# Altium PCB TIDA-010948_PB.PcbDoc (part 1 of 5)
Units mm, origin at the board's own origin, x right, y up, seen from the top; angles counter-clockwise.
Board outline 140 x 180 mm, 4 copper layers (Top Layer, Mid-Layer 1, Mid-Layer 2, Bottom Layer), stack 1.554 mm thick; 481 components, 274 nets, 1278 pads, 301 vias.
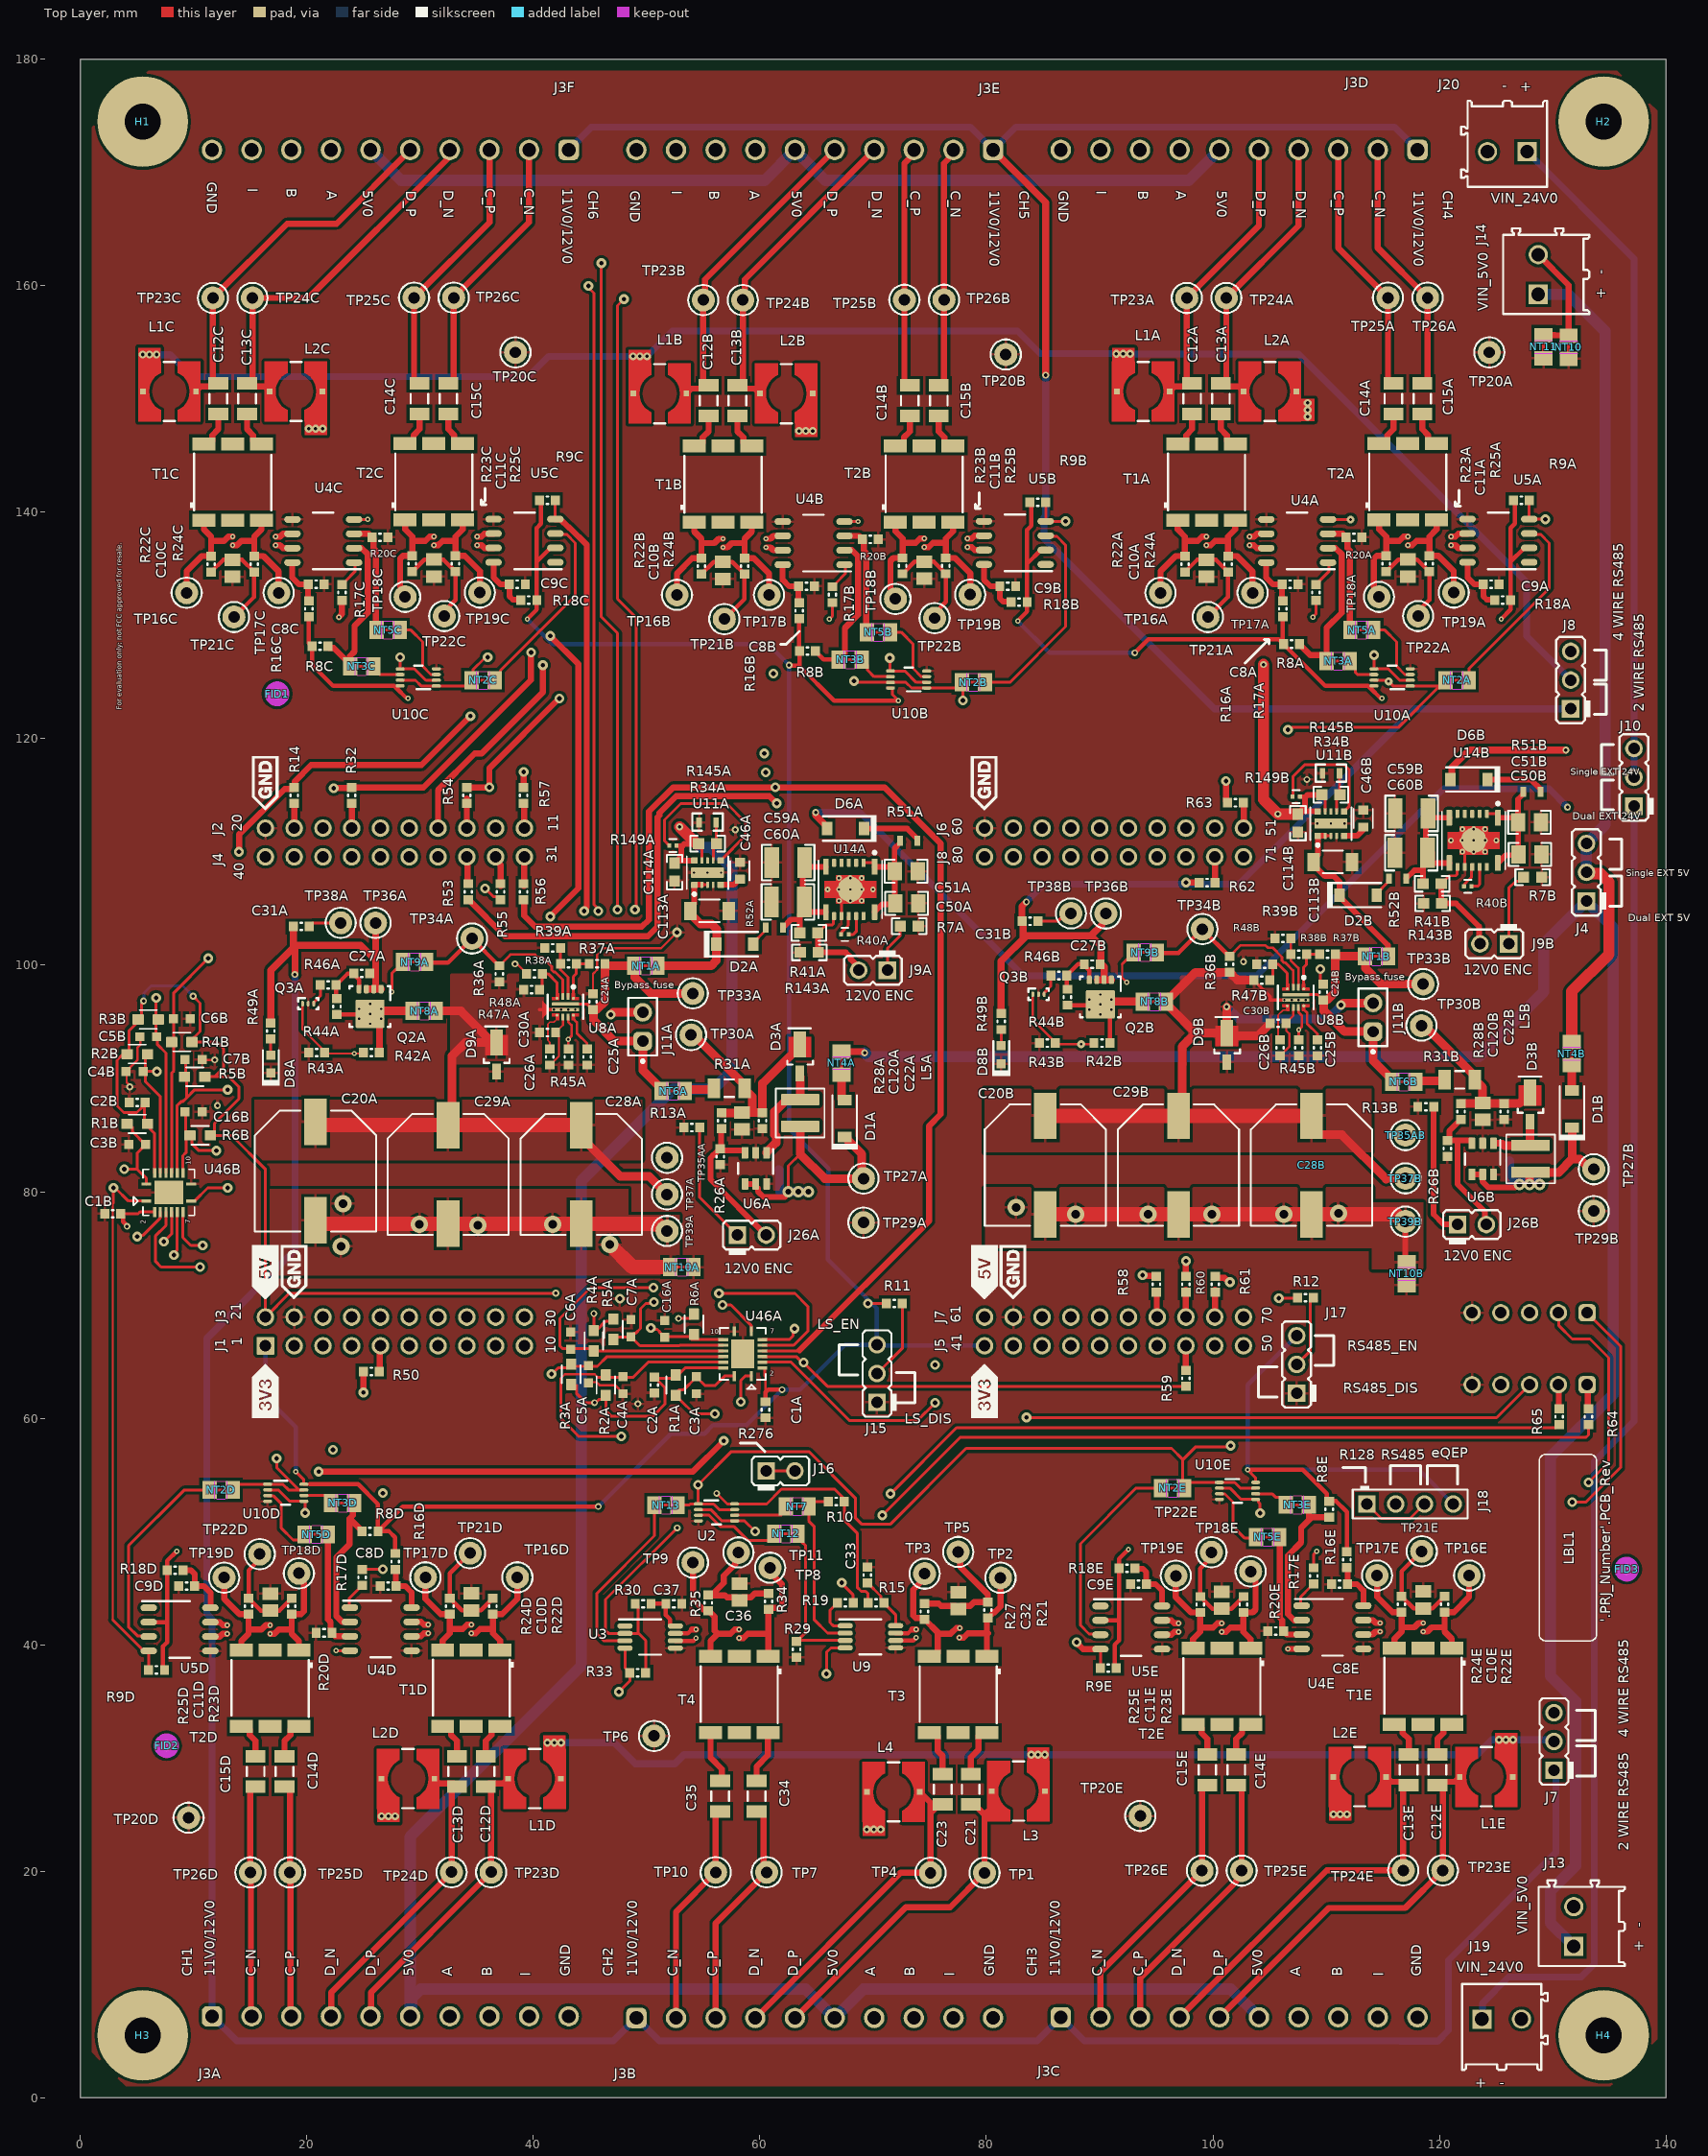
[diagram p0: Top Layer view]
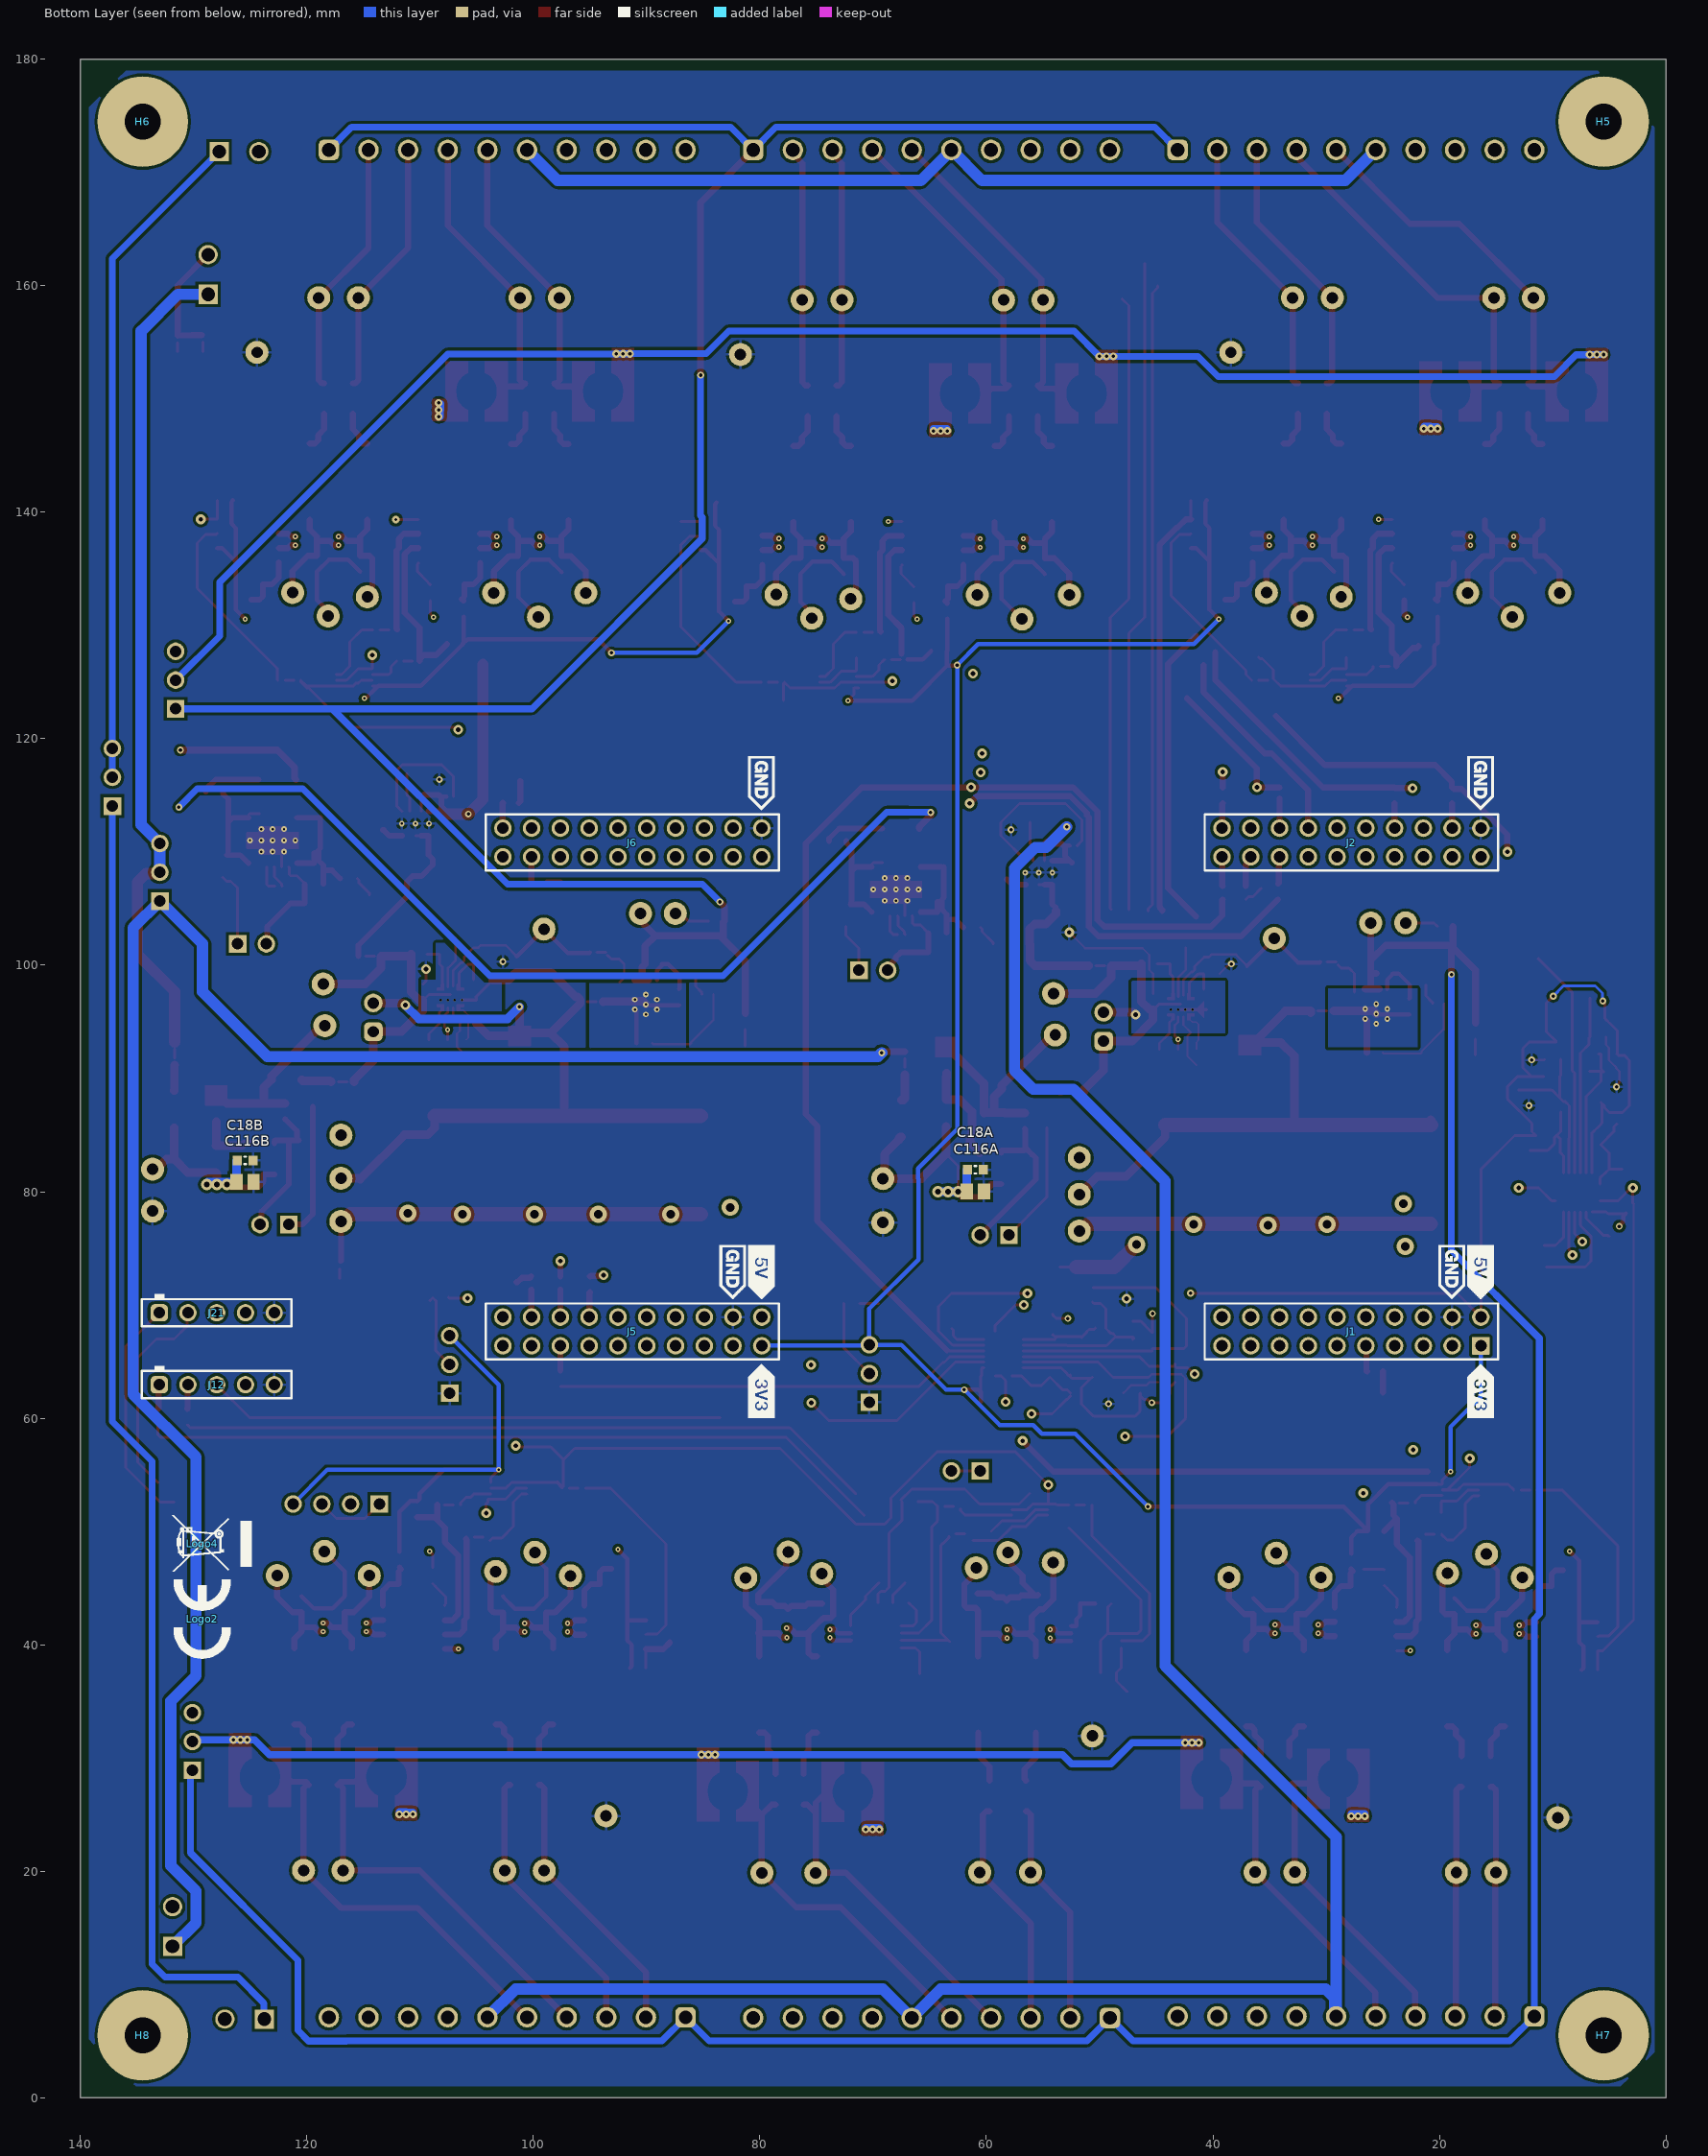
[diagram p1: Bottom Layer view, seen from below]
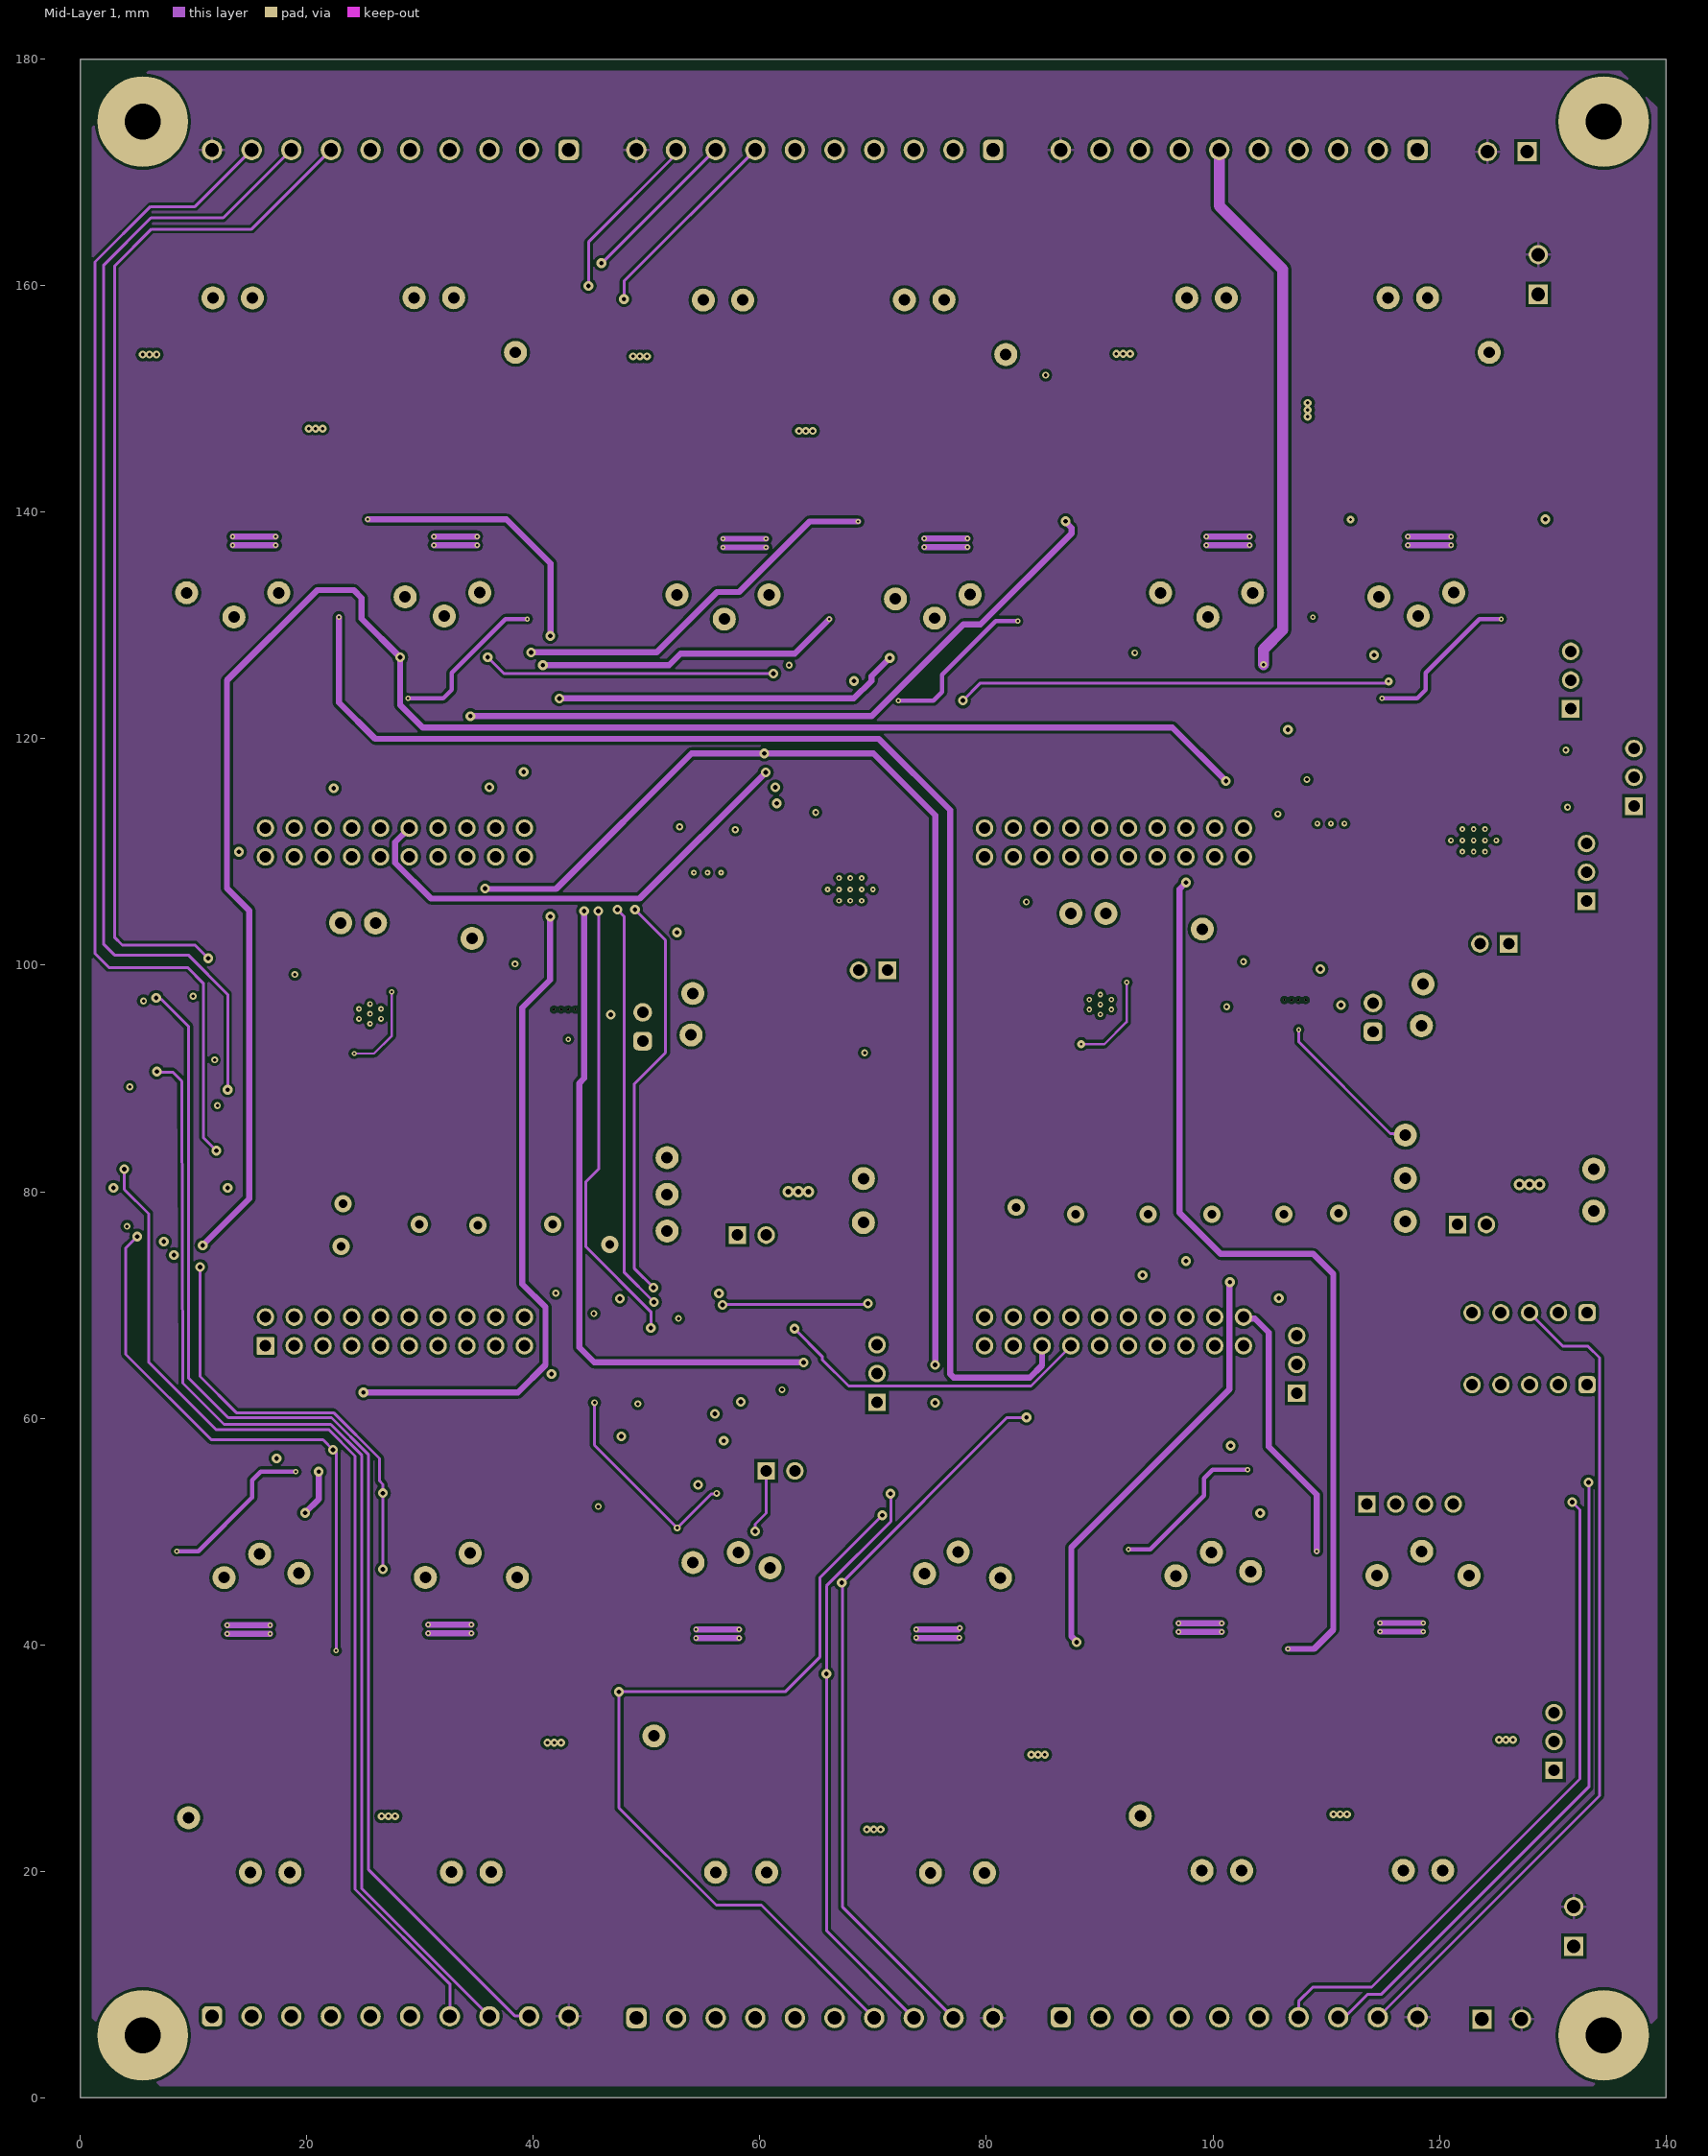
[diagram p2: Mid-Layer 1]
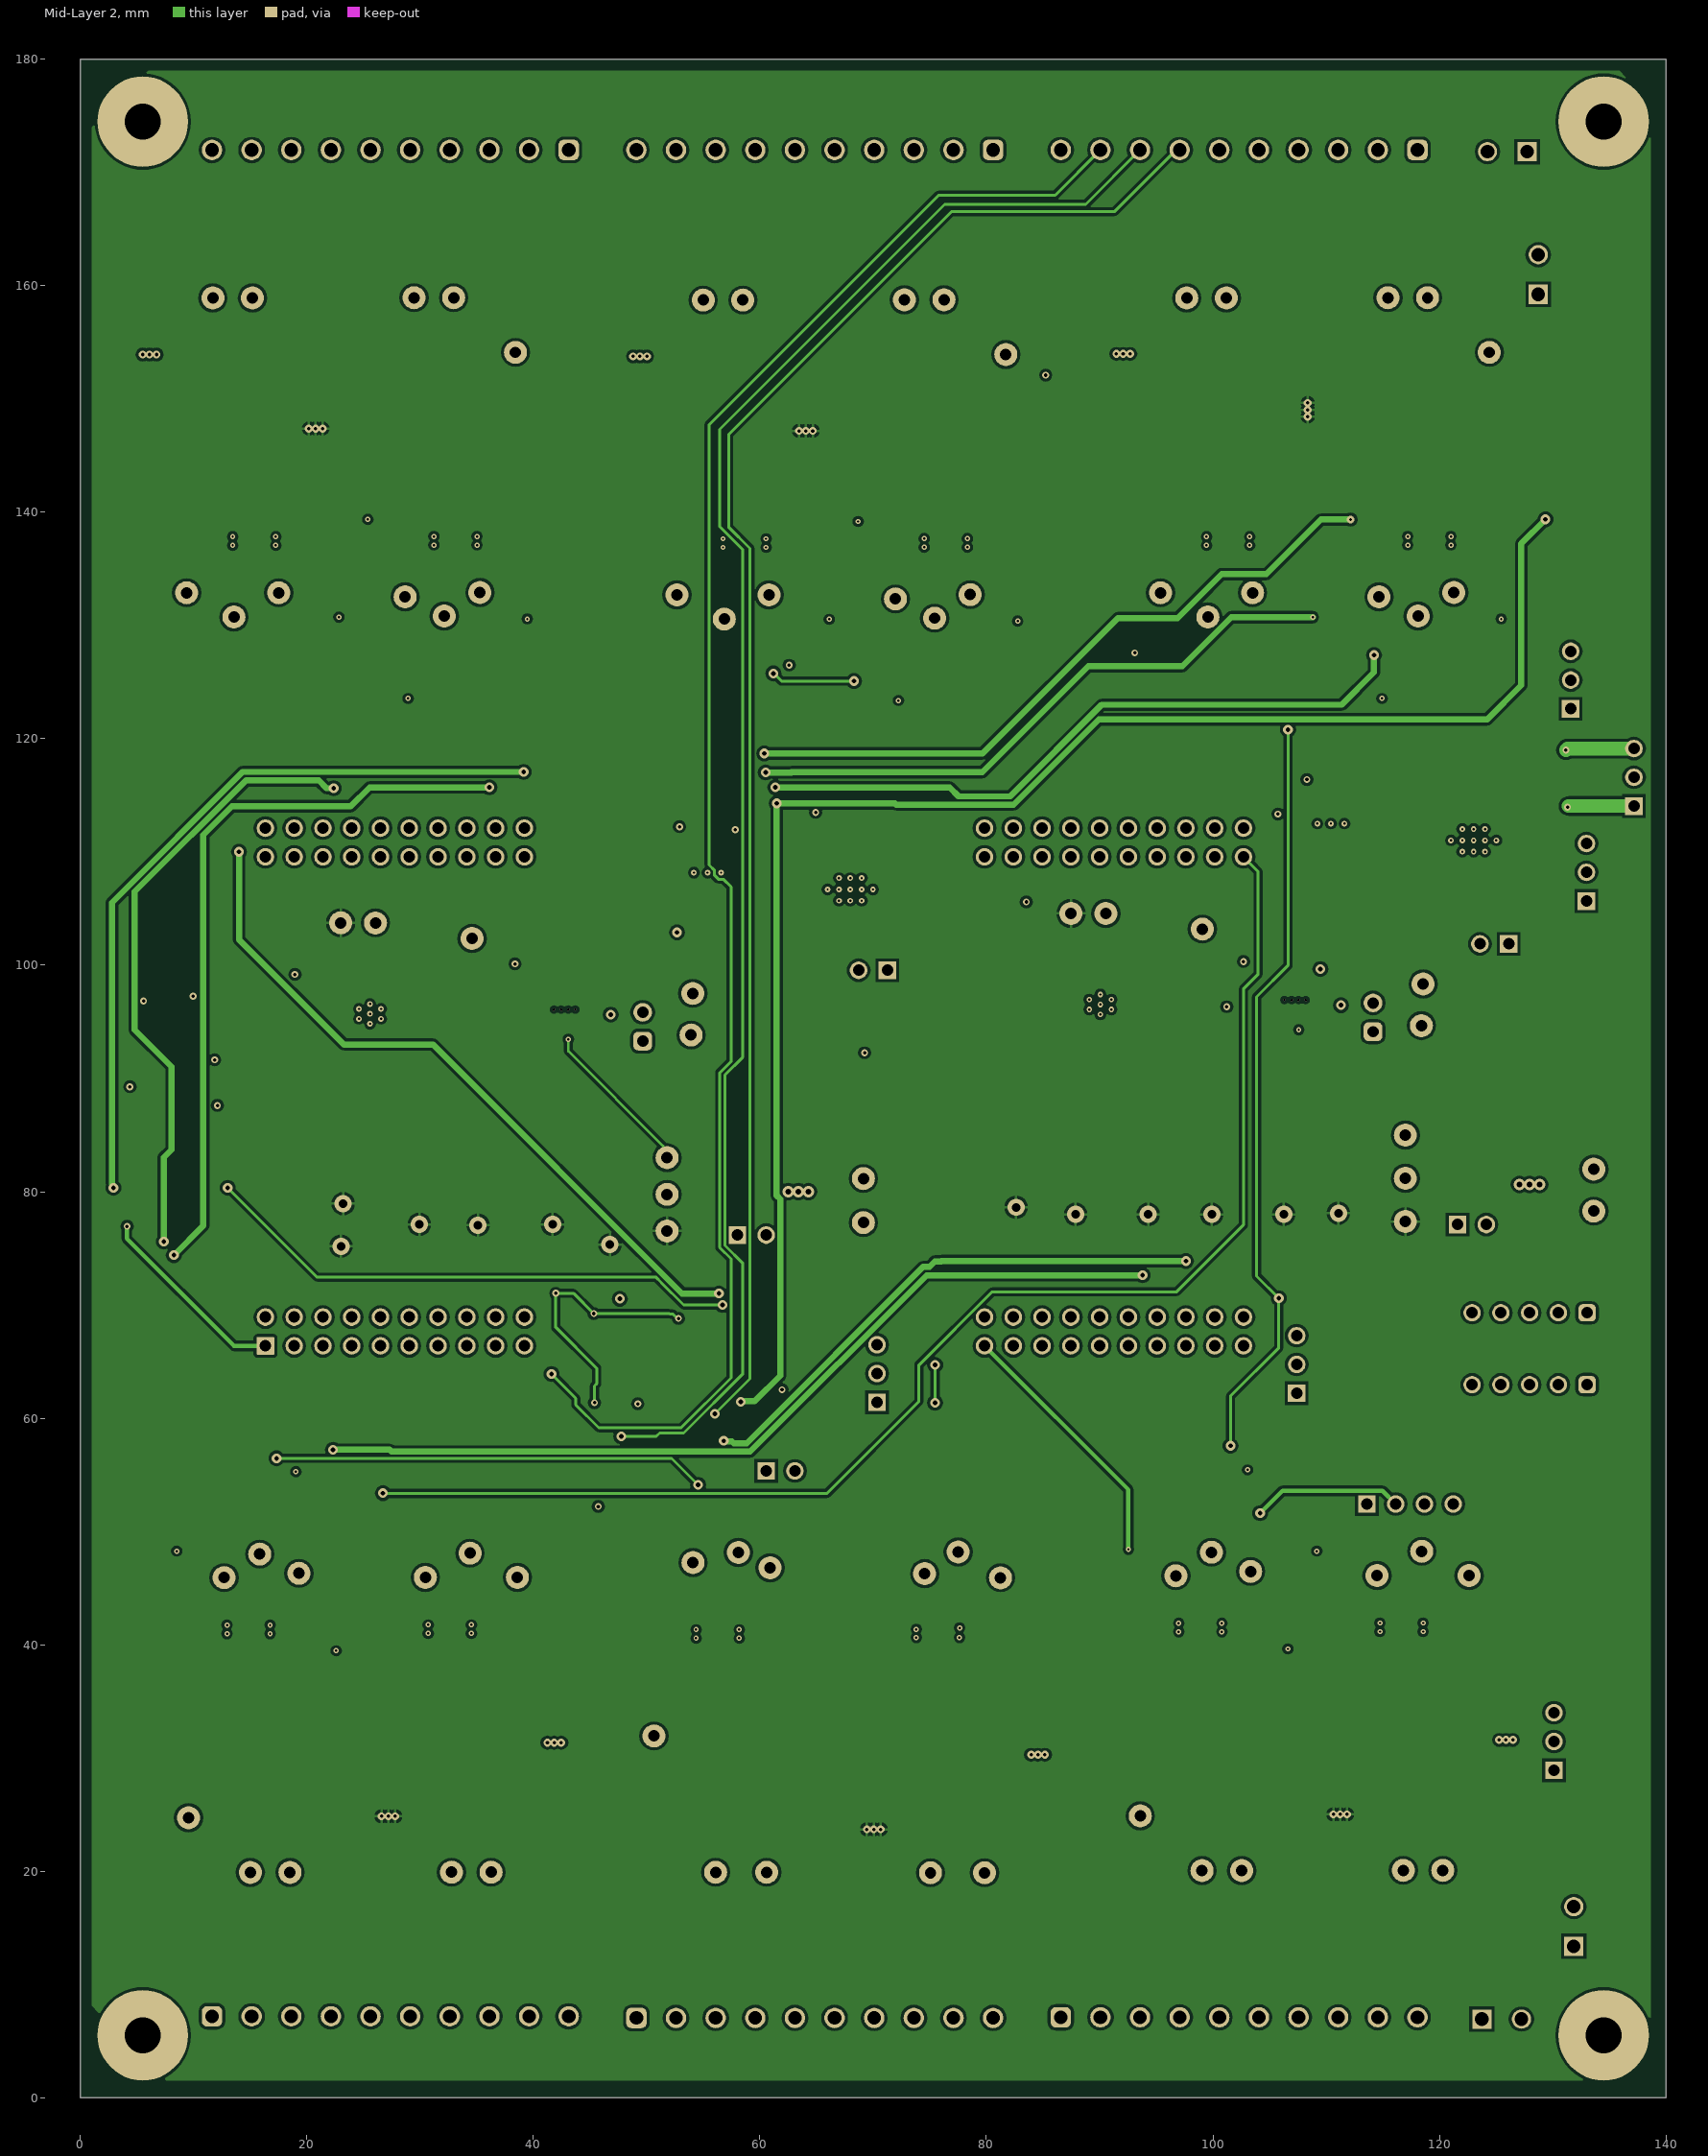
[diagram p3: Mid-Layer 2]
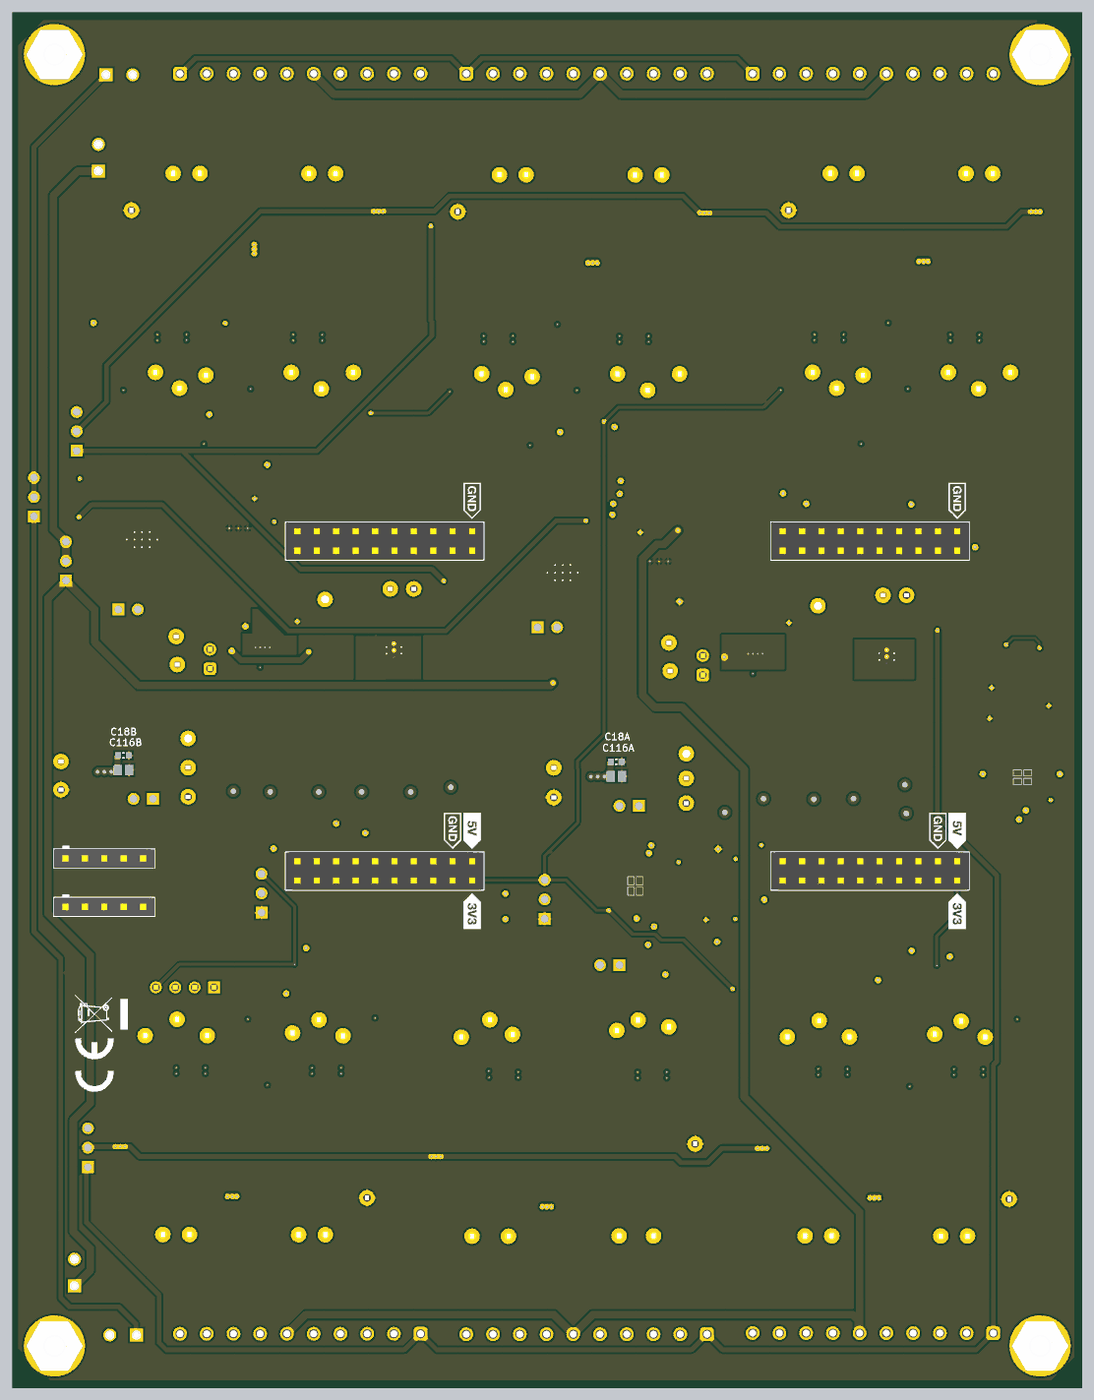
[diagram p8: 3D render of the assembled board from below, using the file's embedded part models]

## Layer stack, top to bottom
Top Solder: solder mask 0.0102, Solder Resist, Dk 3.5
Top Layer: signal copper 0.0356
Dielectric2: dielectric 0.254, FR-4, Dk 4.2
Mid-Layer 1: signal copper 0.0356
Dielectric1: core 0.9034, FR-4 High Tg, Dk 4.2
Mid-Layer 2: signal copper 0.0356
Dielectric3: dielectric 0.254, FR-4, Dk 4.2
Bottom Layer: signal copper 0.0356
Bottom Solder: solder mask 0.0102, Solder Resist, Dk 3.5

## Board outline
0,0 140,0 140,180 0,180

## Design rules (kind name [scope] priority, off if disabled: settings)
AcuteAngle [All] p1: minimum=4.50000000000000E+0001 checktracksonly=FALSE
AssemblyTestPointUsage [All] p1: valid=2
BoardOutlineClearance BoardOutlineClearance_MountingHoles [OnCopper and InComponentClass('Mounting Holes')] p1: gap=1 ignorepadtopadclearanceinfootprint=FALSE
BoardOutlineClearance BoardOutlineClearance_Poly [OnCopper and IsPoly] p2: gap=0.635 ignorepadtopadclearanceinfootprint=FALSE
BoardOutlineClearance [OnCopper and Not InComponentClass('Logo') and not InComponentClass('FiducialMark') and not InRegion(1000,500,4000,800) and not InPoly] p3: gap=1.016 ignorepadtopadclearanceinfootprint=FALSE
Clearance Clearance_Keepouts [((IsTrack Or IsArc) And Not InPoly) And IsFree and IsKeepOut vs ((IsTrack Or IsArc) And Not InPoly) And IsFree and IsKeepOut] p1: gap=0 ignorepadtopadclearanceinfootprint=FALSE
Clearance Clearance_Poly [InPolygon] p2: gap=0.254 ignorepadtopadclearanceinfootprint=TRUE
Clearance Clearance_FiducialMark [IsKeepOut and InComponentClass('FiducialMark') vs IsPad and InComponentClass('FiducialMark')] p3: gap=0 ignorepadtopadclearanceinfootprint=FALSE
Clearance [All] p4: gap=0.2 ignorepadtopadclearanceinfootprint=TRUE
ComponentClearance ComponentClearance_MountingHoles_FiducialMarks [InComponentClass('Mounting Holes') vs InComponentClass('FiducialMark')] p1: gap=1.27 collisioncheckmode=3 verticalgap=0.254 showdistances=FALSE
ComponentClearance ComponentClearance_Shunt [InComponentClass('Header') vs InComponentClass('Shunt')] p2: gap=0 collisioncheckmode=3 verticalgap=0 showdistances=FALSE
ComponentClearance ComponentClearance_Logo [InComponentClass('Logo')] p3: gap=0.762 collisioncheckmode=3 verticalgap=0.254 showdistances=FALSE
ComponentClearance ComponentClearance_ScrewToNut [(HasFootprint('NY PMS 440 0025 PH')) vs (HasFootprint('Keystone_1902C'))] p4: gap=0.127 collisioncheckmode=3 verticalgap=0.254 showdistances=FALSE
ComponentClearance ComponentClearance_MountingHoles [InComponentClass('Mounting Holes')] p5: gap=2.54 collisioncheckmode=3 verticalgap=2540 showdistances=FALSE
ComponentClearance ComponentClearance_SmallPassives [HasFootprint('0201*') or HasFootprint('0402*') or HasFootprint('0508') or HasFootprint('0603*') or HasFootprint('0612') or HasFootprint('0805*') or HasFootprint('0815*') or HasFootprint('0830*') or HasFootprint('1206*') or HasFootprint('1210*') or HasFootprint('1808*') or HasFootprint('1812*') or HasFootprint('1825*') or HasFootprint('2010*') or HasFootprint('2220*') or HasFootprint('2225*') or HasFootprint('2512*') or HasFootprint('2728*') or HasFootprint('3518*') vs HasFootprint('0201*') or HasFootprint('0402*') or HasFootprint('0508') or HasFootprint('0603*') or HasFootprint('0612') or HasFootprint('0805*') or HasFootprint('0815*') or HasFootprint('0830*') or HasFootprint('1206*') or HasFootprint('1210*') or HasFootprint('1808*') or HasFootprint('1812*') or HasFootprint('1825*') or HasFootprint('2010*') or HasFootprint('2220*') or HasFootprint('2225*') or HasFootprint('2512*') or HasFootprint('2728*') or HasFootprint('3518*')] p6: gap=0.38 collisioncheckmode=3 verticalgap=0.254 showdistances=FALSE
ComponentClearance ComponentClearance_THtoSMT [IsThruComponent vs IsSMTComponent] p7: gap=0.762 collisioncheckmode=3 verticalgap=0.762 showdistances=FALSE
ComponentClearance ComponentClearance_THtoTH [IsThruComponent vs IsThruComponent] p8: gap=0.508 collisioncheckmode=3 verticalgap=0.762 showdistances=FALSE
ComponentClearance [All] p9: gap=0.508 collisioncheckmode=3 verticalgap=0.254 showdistances=FALSE
FabricationTestPointUsage TestPointUsage [All] p1: valid=2 allowmultiple=FALSE
FabricationTestpoint Testpoint [All] p1: side=3 testpointundercomponent=TRUE minsize=1.016 maxsize=2.54 preferedsize=1.524 minholesize=0 maxholesize=1.016 preferedholesize=0.813 testpointgrid=0.025 allowsidetop=TRUE allowsidebottom=TRUE usegrid=TRUE gridtolerance=0
FanoutControl Fanout_LCC [IsLCC] p1: bgadir=Out bgaviamode=Centered fanoutstyle=Auto fanoutdirection=Alternating viagrid=0.025 // Fanout_LCC (Default Rule)
FanoutControl Fanout_BGA [IsBGA] p2: bgadir=Out bgaviamode=Centered fanoutstyle=Auto fanoutdirection=Alternating viagrid=0.025 // Fanout_BGA (Default Rule)
FanoutControl Fanout_Default [All] p4: bgadir=Out bgaviamode=Centered fanoutstyle=Auto fanoutdirection=Alternating viagrid=0.025 // Fanout_Default (Default Rule)
FanoutControl Fanout_Small [(CompPinCount < 5)] p5: bgadir=Out bgaviamode=Centered fanoutstyle=Auto fanoutdirection=OutThenIn viagrid=0.025 // Fanout_Small (Default Rule)
HoleSize [All] p1: absolutevalues=TRUE maxlimit=6.375 minlimit=0.2 maxpercent=80.000 minpercent=20.000
MinimumAnnularRing MinimumAnnularRing_ThermalPadVias [IsVia and InAnyComponent] p1: minimumring=0.15
MinimumAnnularRing [All] p2: minimumring=0.2
MinimumSolderMaskSliver MinimumSolderMaskSliver_Logo [InComponentClass('Logo') vs InComponentClass('Logo')] p1: minsoldermaskwidth=0.018
MinimumSolderMaskSliver [All] p2: minsoldermaskwidth=0.1
PlaneConnect [All] p1: planeconnectstyle=Relief reliefexpansion=0.254 reliefentries=4 reliefconductorwidth=0.254 reliefairgap=0.254
PolygonConnect [All] p1: connectstyle=Relief reliefconductorwidth=0.254 reliefentries=4 polygonreliefangle="90 Angle" airgapwidth=0.254
RoomDefinition RoomDefinition_8 [InComponentClass('U_Buck_converters2')] p1: confinementstyle=ConfineIn formatcopy=TRUE lockcomponents=FALSE outline 130.179,104.372 106.118,104.372 106.118,117.934 130.179,117.934
RoomDefinition RoomDefinition_9 [InComponentClass('U_Level_shifter_2')] p2: confinementstyle=ConfineIn formatcopy=TRUE lockcomponents=FALSE outline 1.649,77.186 1.649,96.196 11.962,96.196 11.962,77.186
RoomDefinition RoomDefinition_3 [InComponentClass('U_Communication_2')] p3: confinementstyle=ConfineIn formatcopy=TRUE lockcomponents=FALSE outline 88.3,122.813 46.3,122.813 46.3,160.813 88.3,160.813
RoomDefinition RoomDefinition_4 [InComponentClass('U_Communication_3')] p4: confinementstyle=ConfineIn formatcopy=TRUE lockcomponents=FALSE outline 45,123 3,123 3,161 45,161
RoomDefinition RoomDefinition_2 [InComponentClass('U_Communication_1')] p5: confinementstyle=ConfineIn formatcopy=TRUE lockcomponents=FALSE outline 131,123 89,123 89,161 131,161
RoomDefinition RoomDefinition_10 [InComponentClass('U_Level_shifter_1')] p6: confinementstyle=ConfineIn formatcopy=TRUE lockcomponents=FALSE outline 61.364,59.543 42.355,59.543 42.355,69.857 61.364,69.857
RoomDefinition RoomDefinition_7 [InComponentClass('U_Buck_converters1')] p7: confinementstyle=ConfineIn formatcopy=TRUE lockcomponents=FALSE outline 75.133,100.045 51.071,100.045 51.071,113.607 75.133,113.607
RoomDefinition [InComponentClass('U_Power_2')] p8: confinementstyle=ConfineIn formatcopy=TRUE lockcomponents=FALSE outline 135.388,73.026 79.28,73.026 79.28,106.169 135.388,106.169
RoomDefinition RoomDefinition_1 [InComponentClass('U_Power_1')] p9: confinementstyle=ConfineIn formatcopy=TRUE lockcomponents=FALSE outline 70.894,72.197 14.787,72.197 14.787,105.341 70.894,105.341
RoomDefinition RoomDefinition_11 [InComponentClass('U_Communication_5V0')] p10: confinementstyle=ConfineIn formatcopy=TRUE lockcomponents=FALSE outline 86.559,17.927 45.559,17.927 45.559,56.509 86.559,56.509
RoomDefinition RoomDefinition_6 [InComponentClass('U_Communication_5')] p11: confinementstyle=ConfineIn formatcopy=TRUE lockcomponents=FALSE outline 87,56 129,56 129,18 87,18
RoomDefinition RoomDefinition_5 [InComponentClass('U_Communication_4')] p12: confinementstyle=ConfineIn formatcopy=TRUE lockcomponents=FALSE outline 2.958,55.837 44.958,55.837 44.958,17.837 2.958,17.837
RoutingLayers RoutingLayers_1 [All] p1: top layer_v5=TRUE mid layer 1_v5=TRUE mid layer 2_v5=TRUE bottom layer_v5=TRUE
RoutingVias [All] p1: holewidth=0.711 width=1.27 viastyle="Through Hole" minholewidth=0.711 minwidth=1.27 maxholewidth=0.711 maxwidth=1.27
SilkToBoardRegionClearance [Not ((IsComment or IsDesignator) And (Hide <> 'False')) and not InRegion(1000,500,4000,800)] p1:
SilkToSilkClearance SilkToSilkClearance_Pb-FreeLogo [(HasFootprint('Pb-Free_Overlay_Medium') OR HasFootprint('Pb-Free_Overlay_Small')) vs (HasFootprint('Pb-Free_Overlay_Medium') OR HasFootprint('Pb-Free_Overlay_Small'))] p1: silktosilkclearance=0
SilkToSilkClearance [All] p2: silktosilkclearance=0.1
SilkToSolderMaskClearance SilkToComponentPadClearance [(IsPad or IsFill or IsRegion) and InAnycomponent] p1: minsilkscreentomaskgap=0.127 clearancetoexposedcopper=TRUE
SilkToSolderMaskClearance "Silk to Solder Mask Opening" [All] p2: minsilkscreentomaskgap=0.1 clearancetoexposedcopper=FALSE
SolderMaskExpansion [All] p1: expansion=0.05 istentingtop=FALSE
SupplyNets "Schematic Supply Nets_4" [InNet('GND_EXT')] p1: voltage=0.000
SupplyNets "Schematic Supply Nets_3" [InNet('GND_ENC')] p2: voltage=0.000
SupplyNets "Schematic Supply Nets_2" [InNet('LP_3V3')] p3: voltage=0.000
SupplyNets "Schematic Supply Nets_1" [InNet('GND')] p4: voltage=0.000
SupplyNets "Schematic Supply Nets" [InNet('LP_5V0')] p5: voltage=0.000
UnRoutedNet [All] p1: checkbadconnections=TRUE
UnpouredPolygon UnpouredPolygon_1 [All] p1:
UnpouredPolygon [All] p2:
Width [All] p1: maxlimit=0.254 minlimit=0.254 preferedwidth=0.254
13 further rules are at their usual default settings.

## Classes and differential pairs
channel class TIDA-010948_PB_Power: U_Power_1 U_Power_2
channel class TIDA-010948_PB_Level_shifter: U_Level_shifter_1 U_Level_shifter_2
channel class TIDA-010948_PB_Encoder_connector: U_Encoder_connector_1 U_Encoder_connector_2 U_Encoder_connector_3 U_Encoder_connector_4 U_Encoder_connector_5 U_Encoder_connector_6
channel class TIDA-010948_PB_Communication: U_Communication_1 U_Communication_2 U_Communication_3 U_Communication_4 U_Communication_5
channel class TIDA-010948_PB_Buck_converters: U_Buck_converters1 U_Buck_converters2
polygon class PolyDirectConnect: BOTTOM_LAYER_GND_P089 BOTTOM_LAYER_GND_P096 BOTTOM_LAYER_NETNT8A_2_P080 BOTTOM_LAYER_NETNT8B_2_P088 BOTTOM_LAYER_V_BULKA_P083 BOTTOM_LAYER_V_BULKB_P090
component class U_Buck_converters2: C46B C50B C51B C59B C60B C113B C114B D2B D6B J9B R7B R34B R40B R41B R51B R52B R143B R145B R149B U11B U14B
component class U_Buck_converters1: C46A C50A C51A C59A C60A C113A C114A D2A D6A J9A R7A R34A R40A R41A R51A R52A R143A R145A R149A U11A U14A
component class U_Communication_4: C8D C9D C10D C11D C12D C13D C14D C15D L1D L2D NT2D NT3D NT5D R8D R9D R16D R17D R18D R20D R22D R23D R24D R25D T1D T2D TP16D TP17D TP18D TP19D TP20D TP21D TP22D TP23D TP24D TP25D TP26D U4D U5D U10D
component class U_Communication_5: C8E C9E C10E C11E C12E C13E C14E C15E L1E L2E NT2E NT3E NT5E R8E R9E R16E R17E R18E R20E R22E R23E R24E R25E T1E T2E TP16E TP17E TP18E TP19E TP20E TP21E TP22E TP23E TP24E TP25E TP26E U4E U5E U10E
component class U_Communication_5V0: C21 C23 C32 C33 C34 C35 C36 C37 L3 L4 NT7 NT12 NT13 R10 R15 R19 R21 R27 R29 R30 R33 R34 R35 T3 T4 TP1 TP2 TP3 TP4 TP5 TP6 TP7 TP8 TP9 TP10 TP11 U2 U3 U9
component class TIDA-010948_PB: J7 J8 J15 J16 J17 J18 R11 R12
component class U_Level_shifter_2: C1B C2B C3B C4B C5B C6B C7B C16B R1B R2B R3B R4B R5B R6B U46B
component class U_Level_shifter_1: C1A C2A C3A C4A C5A C6A C7A C16A R1A R2A R3A R4A R5A R6A U46A
component class U_Encoder_connector_6: J3F
component class U_Encoder_connector_5: J3E
component class U_Encoder_connector_4: J3D
component class U_Encoder_connector_3: J3C
component class U_Encoder_connector_2: J3B
component class U_Encoder_connector_1: J3A
component class U_Connectors: J1 J2 J4 J5 J6 J10 J12 J13 J14 J19 J20 J21 NT10 NT11 R14 R32 R50 R53 R54 R55 R56 R57 R58 R59 R60 R61 R62 R63 R64 R65
component class U_Communication_3: C8C C9C C10C C11C C12C C13C C14C C15C L1C L2C NT2C NT3C NT5C R8C R9C R16C R17C R18C R20C R22C R23C R24C R25C T1C T2C TP16C TP17C TP18C TP19C TP20C TP21C TP22C TP23C TP24C TP25C TP26C U4C U5C U10C
component class U_Communication_2: C8B C9B C10B C11B C12B C13B C14B C15B L1B L2B NT2B NT3B NT5B R8B R9B R16B R17B R18B R20B R22B R23B R24B R25B T1B T2B TP16B TP17B TP18B TP19B TP20B TP21B TP22B TP23B TP24B TP25B TP26B U4B U5B U10B
component class U_Power_2: C18B C20B C22B C24B C25B C26B C27B C28B C29B C30B C31B C116B C120B D1B D3B D8B D9B J11B J26B L5B NT1B NT4B NT6B NT8B NT9B NT10B Q2B Q3B R13B R26B R28B R31B R36B R37B R38B R39B R42B R43B R44B R45B R46B R47B R48B R49B TP27B TP29B TP30B TP33B TP34B TP35AB TP36B TP37B TP38B TP39B U6B U8B
component class U_Power_1: 2 C18A C20A C22A C24A C25A C26A C27A C28A C29A C30A C31A C116A C120A D1A D3A D8A D9A J11A J26A L5A NT1A NT4A NT6A NT8A NT9A NT10A Q2A Q3A R13A R26A R28A R31A R36A R37A R38A R39A R42A R43A R44A R45A R46A R47A R48A R49A TP27A TP29A TP30A TP33A TP34A TP35AA TP36A TP37A TP38A TP39A U6A U8A
component class U_Communication_1: C8A C9A C10A C11A C12A C13A C14A C15A L1A L2A NT2A NT3A NT5A R8A R9A R16A R17A R18A R20A R22A R23A R24A R25A T1A T2A TP16A TP17A TP18A TP19A TP20A TP21A TP22A TP23A TP24A TP25A TP26A U4A U5A U10A
component class U_Hardware: FID1 FID2 FID3 H1 H2 H3 H4 H5 H6 H7 H8 LBL1 Logo2 Logo3 Logo4 ZZ1 ZZ2 ZZ3 ZZ4

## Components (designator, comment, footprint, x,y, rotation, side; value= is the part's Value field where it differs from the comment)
C1A "GRM188R72A104KA35D" 0603L 60.491,60.744 r270 top value=0.1uF (schematic designator C1)
C1B "GRM188R72A104KA35D" 0603L 2.85,78.059 r180 top value=0.1uF (schematic designator C1)
C2A "GRM188R72A104KA35D" 0603L 50.668,62.914 r270 top value=0.1uF (schematic designator C2)
C2B "GRM188R72A104KA35D" 0603L 5.02,87.882 r180 top value=0.1uF (schematic designator C2)
C3A "885012006085" WCAP-CSGP_0603_L1.6W0.8H0.8_Reflow 54.393,62.914 r270 top (schematic designator C3)
C3B "885012006085" WCAP-CSGP_0603_L1.6W0.8H0.8_Reflow 5.02,84.157 r180 top (schematic designator C3)
C4A "885012006085" WCAP-CSGP_0603_L1.6W0.8H0.8_Reflow 47.926,62.914 r270 top (schematic designator C4)
C4B "885012006085" WCAP-CSGP_0603_L1.6W0.8H0.8_Reflow 4.784,90.6 r180 top (schematic designator C4)
C5A "885012006085" WCAP-CSGP_0603_L1.6W0.8H0.8_Reflow 44.865,63.878 r270 top (schematic designator C5)
C5B "885012006085" WCAP-CSGP_0603_L1.6W0.8H0.8_Reflow 5.984,93.685 r180 top (schematic designator C5)
C6A "885012006085" WCAP-CSGP_0603_L1.6W0.8H0.8_Reflow 43.285,66.843 r90 top (schematic designator C6)
C6B "885012006085" WCAP-CSGP_0603_L1.6W0.8H0.8_Reflow 8.949,95.265 r0 top (schematic designator C6)
C7A "885012006085" WCAP-CSGP_0603_L1.6W0.8H0.8_Reflow 48.608,67.943 r90 top (schematic designator C7)
C7B "885012006085" WCAP-CSGP_0603_L1.6W0.8H0.8_Reflow 9.993,91.685 r0 top (schematic designator C7)
C8A "GRM188R72A104KA35D" 0603L 106.805,133.657 r0 top value=0.1uF (schematic designator C8)
C8B "GRM188R72A104KA35D" 0603L 64.106,133.47 r0 top value=0.1uF (schematic designator C8)
C8C "GRM188R72A104KA35D" 0603L 20.805,133.657 r0 top value=0.1uF (schematic designator C8)
C8D "GRM188R72A104KA35D" 0603L 27.153,45.181 r180 top value=0.1uF (schematic designator C8)
C8E "GRM188R72A104KA35D" 0603L 111.195,45.343 r180 top value=0.1uF (schematic designator C8)
C9A "GRM188R72A104KA35D" 0603L 124.585,133.657 r0 top value=0.1uF (schematic designator C9)
C9B "GRM188R72A104KA35D" 0603L 81.886,133.47 r0 top value=0.1uF (schematic designator C9)
C9C "GRM188R72A104KA35D" 0603L 38.585,133.657 r0 top value=0.1uF (schematic designator C9)
C9D "GRM188R72A104KA35D" 0603L 9.373,45.181 r180 top value=0.1uF (schematic designator C9)
C9E "GRM188R72A104KA35D" 0603L 93.415,45.343 r180 top value=0.1uF (schematic designator C9)
C10A "CGA4J3X7R1H225K125AB" 0805L 99.439,135.054 r270 top value=2.2uF (schematic designator C10)
C10B "CGA4J3X7R1H225K125AB" 0805L 56.74,134.867 r270 top value=2.2uF (schematic designator C10)
C10C "CGA4J3X7R1H225K125AB" 0805L 13.439,135.054 r270 top value=2.2uF (schematic designator C10)
C10D "CGA4J3X7R1H225K125AB" 0805L 34.519,43.784 r90 top value=2.2uF (schematic designator C10)
C10E "CGA4J3X7R1H225K125AB" 0805L 118.561,43.946 r90 top value=2.2uF (schematic designator C10)
C11A "CGA4J3X7R1H225K125AB" 0805L 117.208,135.074 r270 top value=2.2uF (schematic designator C11)
C11B "CGA4J3X7R1H225K125AB" 0805L 74.508,134.887 r270 top value=2.2uF (schematic designator C11)
C11C "CGA4J3X7R1H225K125AB" 0805L 31.208,135.074 r270 top value=2.2uF (schematic designator C11)
C11D "CGA4J3X7R1H225K125AB" 0805L 16.75,43.763 r90 top value=2.2uF (schematic designator C11)
C11E "CGA4J3X7R1H225K125AB" 0805L 100.792,43.926 r90 top value=2.2uF (schematic designator C11)
C12A "ECPU1C474MA5" 1206L 98.169,150.04 r270 top value=0.47uF (schematic designator C12)
C12B "ECPU1C474MA5" 1206L 55.47,149.853 r270 top value=0.47uF (schematic designator C12)
C12C "ECPU1C474MA5" 1206L 12.169,150.04 r270 top value=0.47uF (schematic designator C12)
C12D "ECPU1C474MA5" 1206L 35.789,28.798 r90 top value=0.47uF (schematic designator C12)
C12E "ECPU1C474MA5" 1206L 119.831,28.96 r90 top value=0.47uF (schematic designator C12)
C13A "ECPU1C474MA5" 1206L 100.709,150.04 r270 top value=0.47uF (schematic designator C13)
C13B "ECPU1C474MA5" 1206L 58.01,149.853 r270 top value=0.47uF (schematic designator C13)
C13C "ECPU1C474MA5" 1206L 14.709,150.04 r270 top value=0.47uF (schematic designator C13)
C13D "ECPU1C474MA5" 1206L 33.249,28.798 r90 top value=0.47uF (schematic designator C13)
C13E "ECPU1C474MA5" 1206L 117.291,28.96 r90 top value=0.47uF (schematic designator C13)
C14A "ECPU1C474MA5" 1206L 115.938,150.04 r270 top value=0.47uF (schematic designator C14)
C14B "ECPU1C474MA5" 1206L 73.238,149.853 r270 top value=0.47uF (schematic designator C14)
C14C "ECPU1C474MA5" 1206L 29.938,150.04 r270 top value=0.47uF (schematic designator C14)
C14D "ECPU1C474MA5" 1206L 18.02,28.798 r90 top value=0.47uF (schematic designator C14)
C14E "ECPU1C474MA5" 1206L 102.062,28.96 r90 top value=0.47uF (schematic designator C14)
C15A "ECPU1C474MA5" 1206L 118.489,150.04 r270 top value=0.47uF (schematic designator C15)
C15B "ECPU1C474MA5" 1206L 75.79,149.853 r270 top value=0.47uF (schematic designator C15)
C15C "ECPU1C474MA5" 1206L 32.489,150.04 r270 top value=0.47uF (schematic designator C15)
C15D "ECPU1C474MA5" 1206L 15.469,28.798 r90 top value=0.47uF (schematic designator C15)
C15E "ECPU1C474MA5" 1206L 99.511,28.96 r90 top value=0.47uF (schematic designator C15)
C16A "885012006085" WCAP-CSGP_0603_L1.6W0.8H0.8_Reflow 51.586,67.887 r90 top (schematic designator C16)
C16B "885012006085" WCAP-CSGP_0603_L1.6W0.8H0.8_Reflow 9.993,87.053 r0 top (schematic designator C16)
C18A "GRM188R72A104KA35D" 0603L 60.971,81.938 r180 bottom value=0.1uF (schematic designator C18)
C18B "GRM188R72A104KA35D" 0603L 125.464,82.767 r180 bottom value=0.1uF (schematic designator C18)
C20A "EEE-FK1C681P" SM_RADIAL_G 20.757,81.821 r270 top value=680uF (schematic designator C20)
C20B "EEE-FK1C681P" SM_RADIAL_G 85.205,82.35 r270 top value=680uF (schematic designator C20)
C21 "ECPU1C474MA5" 1206L 78.617,27.232 r90 top value=0.47uF
C22A "GRM188R72A104KA35D" 0603L 60.226,86.258 r270 top value=0.1uF (schematic designator C22)
C22B "GRM188R72A104KA35D" 0603L 125.732,87.086 r270 top value=0.1uF (schematic designator C22)
C23 "ECPU1C474MA5" 1206L 76.14,27.232 r90 top value=0.47uF
C24A "GRM188R72A104KA35D" 0603L 45.261,96.784 r90 top value=0.1uF (schematic designator C24)
C24B "GRM188R72A104KA35D" 0603L 109.755,97.612 r90 top value=0.1uF (schematic designator C24)
C25A "GRM1885C1H222JA01D" 0603L 44.736,91.889 r270 top value=2200pF (schematic designator C25)
C25B "GRM1885C1H222JA01D" 0603L 109.23,92.717 r270 top value=2200pF (schematic designator C25)
C26A "GRM188R71H562KA01D" 0603L 41.439,91.889 r270 top value=5600pF (schematic designator C26)
C26B "GRM188R71H562KA01D" 0603L 105.933,92.717 r270 top value=5600pF (schematic designator C26)
C27A "GCM188R72A153KA37D" 0603L 24.85,99.274 r180 top value=0.015uF (schematic designator C27)
C27B "GCM188R72A153KA37D" 0603L 89.344,100.103 r180 top value=0.015uF (schematic designator C27)
C28A "EEE-FK1C681P" SM_RADIAL_G 44.217,81.521 r270 top value=680uF (schematic designator C28)
C28B "EEE-FK1C681P" SM_RADIAL_G 108.711,82.35 r270 top value=680uF (schematic designator C28)
C29A "EEE-FK1C681P" SM_RADIAL_G 32.464,81.521 r270 top value=680uF (schematic designator C29)
C29B "EEE-FK1C681P" SM_RADIAL_G 96.958,82.35 r270 top value=680uF (schematic designator C29)
C30A "GRM188R72A104KA35D" 0603L 41.254,94.048 r0 top value=0.1uF (schematic designator C30)
C30B "GRM188R72A104KA35D" 0603L 105.748,94.876 r0 top value=0.1uF (schematic designator C30)
C31A "GRM188R72A104KA35D" 0603L 19.493,103.429 r0 top value=0.1uF (schematic designator C31)
C31B "GRM188R72A104KA35D" 0603L 83.843,103.879 r0 top value=0.1uF (schematic designator C31)
C32 "CGA4J3X7R1H225K125AB" 0805L 77.51,43.894 r90 top value=2.2uF
C33 "GRM188R72A104KA35D" 0603L 69.482,46.162 r90 top value=0.1uF
C34 "ECPU1C474MA5" 1206L 59.709,26.63 r90 top value=0.47uF
C35 "ECPU1C474MA5" 1206L 56.488,26.63 r90 top value=0.47uF
C36 "CGA4J3X7R1H225K125AB" 0805L 58.202,44.639 r90 top value=2.2uF
C37 "GRM188R72A104KA35D" 0603L 52.399,43.615 r0 top value=0.1uF
C46A "CC0603KRX7R7BB102" FP-CC0603KRX7R7BB102_0603-MFG 58.233,108.349 r270 top value=1nF (schematic designator C46)
C46B "CC0603KRX7R7BB102" FP-CC0603KRX7R7BB102_0603-MFG 113.28,112.951 r270 top value=1nF (schematic designator C46)
C50A "GRM21BC71H475KE11K" 0805_HV 72.954,105.47 r180 top value=4.7uF (schematic designator C50)
C50B "GRM21BC71H475KE11K" 0805_HV 128.001,109.797 r180 top value=4.7uF (schematic designator C50)
C51A "GRM21BC71H475KE11K" 0805_HV 72.908,108.3 r180 top value=4.7uF (schematic designator C51)
C51B "GRM21BC71H475KE11K" 0805_HV 127.955,112.628 r180 top value=4.7uF (schematic designator C51)
C59A "GRM32ER61C476KE15L" 1210_270 62.498,109.079 r180 top value=47uF (schematic designator C59)
C59B "GRM32ER61C476KE15L" 1210_270 117.545,113.407 r180 top value=47uF (schematic designator C59)
C60A "GRM32ER61C476KE15L" 1210_270 62.47,105.606 r0 top value=47uF (schematic designator C60)
C60B "GRM32ER61C476KE15L" 1210_270 117.517,109.934 r0 top value=47uF (schematic designator C60)
C113A "C3216X5R1E106K160AB" 1206_180 55.541,104.796 r0 top value=10uF (schematic designator C113)
C113B "C3216X5R1E106K160AB" 1206_180 110.588,109.123 r0 top value=10uF (schematic designator C113)
C114A "GRM187R61A226ME15D" 0603 52.461,108.23 r270 top value=22uF (schematic designator C114)
C114B "GRM187R61A226ME15D" 0603 107.508,112.557 r270 top value=22uF (schematic designator C114)
C116A "GRM21BR71A106KE51L" 0805L 60.971,80.035 r180 bottom value=10uF (schematic designator C116)
C116B "GRM21BR71A106KE51L" 0805L 125.464,80.863 r180 bottom value=10uF (schematic designator C116)
C120A "GRM21BC71H475KE11K" 0805L 58.421,86.258 r270 top value=4.7uF (schematic designator C120)
C120B "GRM21BC71H475KE11K" 0805L 123.824,87.086 r270 top value=4.7uF (schematic designator C120)
D1A "MBR0560-TP" SOD-123 67.487,86.463 r90 top value=60V (schematic designator D1)
D1B "MBR0560-TP" SOD-123 131.726,87.292 r90 top value=60V (schematic designator D1)
D2A "MBR0560-TP" SOD-123 57.784,101.861 r0 top value=60V (schematic designator D2)
D2B "MBR0560-TP" SOD-123 112.831,106.189 r0 top value=60V (schematic designator D2)
D3A "STPS120M" DO-216AA 63.524,91.848 r270 top value=20V (schematic designator D3)
D3B "STPS120M" DO-216AA 128.018,87.594 r270 top value=20V (schematic designator D3)
D6A "MBR0560-TP" SOD-123 67.572,112.072 r180 top value=60V (schematic designator D6)
D6B "MBR0560-TP" SOD-123 122.619,116.399 r180 top value=60V (schematic designator D6)
D8A "150060GS75000" WL-SMCW_GREEN 16.809,91.273 r90 top value=Green (schematic designator D8)
D8B "150060GS75000" WL-SMCW_GREEN 81.303,92.102 r90 top value=Green (schematic designator D8)
D9A "STPS120M" DO-216AA 36.735,92.016 r270 top value=20V (schematic designator D9)
D9B "STPS120M" DO-216AA 101.229,92.845 r270 top value=20V (schematic designator D9)
FID1 "Fiducial" Fiducial10-20 17.359,123.971 r0 top
FID2 "Fiducial" Fiducial10-20 7.599,31.072 r0 top
FID3 "Fiducial" Fiducial10-20 136.531,46.666 r0 top
H1 "NY PMS 440 0025 PH" "NY PMS 440 0025 PH" 5.5,174.5 r0 top
H2 "NY PMS 440 0025 PH" "NY PMS 440 0025 PH" 134.5,174.5 r0 top
H3 "NY PMS 440 0025 PH" "NY PMS 440 0025 PH" 5.5,5.5 r0 top
H4 "NY PMS 440 0025 PH" "NY PMS 440 0025 PH" 134.5,5.5 r0 top
H5 "1902C" Keystone_1902C 5.5,174.5 r180 bottom
H6 "1902C" Keystone_1902C 134.5,174.5 r180 bottom
H7 "1902C" Keystone_1902C 5.5,5.5 r180 bottom
H8 "1902C" Keystone_1902C 134.5,5.5 r180 bottom
J1 "BoosterPack_40pin_J1J3" BoosterPack_40pin_J1J3 27.767,67.657 r270 bottom
J2 "BoosterPack_40pin_J2J4" BoosterPack_40pin_J2J4 27.767,110.837 r270 bottom
J3A "ED555/10DS" On-Shore_ED555_10DS 27.365,7.181 r0 top (schematic designator J3)
J3B "ED555/10DS" On-Shore_ED555_10DS 64.841,7.032 r0 top (schematic designator J3)
J3C "ED555/10DS" On-Shore_ED555_10DS 102.317,7.09 r0 top (schematic designator J3)
J3D "ED555/10DS" On-Shore_ED555_10DS 102.317,172 r180 top (schematic designator J3)
J3E "ED555/10DS" On-Shore_ED555_10DS 64.841,172 r180 top (schematic designator J3)
J3F "ED555/10DS" On-Shore_ED555_10DS 27.365,172 r180 top (schematic designator J3)
J4 "GBC03SAAN" Sullins_Gxx03SAAN 132.988,108.207 r90 top
J5 "BoosterPack_40pin_J5J7" BoosterPack_40pin_J5J7 91.267,67.657 r270 bottom
J6 "BoosterPack_40pin_J6J8" BoosterPack_40pin_J6J8 91.267,110.837 r270 bottom
J7 "GBC03SAAN" Sullins_Gxx03SAAN 130.118,31.449 r90 top
J8 "GBC03SAAN" Sullins_Gxx03SAAN 131.592,125.184 r90 top
J9A "GBC02SAAN" Sullins_Gxx02SAAN 69.984,99.556 r180 top (schematic designator J9)
J9B "GBC02SAAN" Sullins_Gxx02SAAN 124.851,101.887 r180 top (schematic designator J9)
J10 "GBC03SAAN" Sullins_Gxx03SAAN 137.181,116.594 r90 top
J11A "TSW-102-07-G-S" TSW-102-07-G-S 49.647,94.573 r90 top (schematic designator J11)
J11B "TSW-102-07-G-S" TSW-102-07-G-S 114.141,95.401 r90 top (schematic designator J11)
J12 "Receptacle_5x1" Samtec_SSQ-105-01-x-S 127.97,62.958 r180 bottom
J13 "1984617" Phoenix_1984617 131.868,15.115 r90 top
J14 "1984617" Phoenix_1984617 128.733,161 r90 top
J15 "GBC03SAAN" Sullins_Gxx03SAAN 70.338,63.946 r90 top
J16 "GBC02SAAN" Sullins_Gxx02SAAN 61.818,55.344 r0 top
J17 "GBC03SAAN" Sullins_Gxx03SAAN 107.398,64.743 r90 top
J18 "PBC04SAAN" Sullins_xxC04SAAN 117.416,52.42 r0 top
J19 "1984617" Phoenix_1984617 125.5,6.935 r0 top
J20 "1984617" Phoenix_1984617 126,171.85 r180 top
J21 "Receptacle_5x1" Samtec_SSQ-105-01-x-S 127.97,69.308 r180 bottom
J26A "GBC02SAAN" Sullins_Gxx02SAAN 59.279,76.171 r0 top (schematic designator J26)
J26B "GBC02SAAN" Sullins_Gxx02SAAN 122.87,77.1 r0 top (schematic designator J26)
L1A "744043101" WE-TPC_4828 93.851,150.675 r180 top value=100uH (schematic designator L1)
L1B "744043101" WE-TPC_4828 51.152,150.488 r180 top value=100uH (schematic designator L1)
L1C "744043101" WE-TPC_4828 7.851,150.675 r180 top value=100uH (schematic designator L1)
L1D "744043101" WE-TPC_4828 40.107,28.163 r0 top value=100uH (schematic designator L1)
L1E "744043101" WE-TPC_4828 124.149,28.325 r0 top value=100uH (schematic designator L1)
L2A "744043101" WE-TPC_4828 105.027,150.675 r180 top value=100uH (schematic designator L2)
L2B "744043101" WE-TPC_4828 62.328,150.488 r180 top value=100uH (schematic designator L2)
L2C "744043101" WE-TPC_4828 19.027,150.675 r180 top value=100uH (schematic designator L2)
L2D "744043101" WE-TPC_4828 28.931,28.163 r0 top value=100uH (schematic designator L2)
L2E "744043101" WE-TPC_4828 112.973,28.325 r0 top value=100uH (schematic designator L2)
L3 "744043101" WE-TPC_4828 82.832,27.063 r0 top value=100uH
L4 "744043101" WE-TPC_4828 71.8,26.983 r0 top value=100uH
L5A "XAL4030-472MEC" FP-XAL4030-472MEC_SMD2-MFG 63.56,86.95 r90 top value=4.7µH (schematic designator L5)
L5B "XAL4030-472MEC" FP-XAL4030-472MEC_SMD2-MFG 128.053,82.895 r90 top value=4.7µH (schematic designator L5)
LBL1 "THT-14-423-10" Label_650x200 131.352,48.571 r90 top
Logo2 "CE Mark" CE_Mark_5mm 129.251,42.258 r90 bottom
Logo3 "FCC disclaimer" FCC_disclaimer 60.223,297.465 r0 top
Logo4 "WEEE logo" WEEE_Minimum 129.251,48.906 r90 bottom
NT1A "Net-Tie" Net-Tie_0805_HV_NoOverlay 49.937,99.955 r180 top net-tie (schematic designator NT1)
NT1B "Net-Tie" Net-Tie_0805_HV_NoOverlay 114.431,100.783 r180 top net-tie (schematic designator NT1)
NT2A "Net-Tie" Net-Tie_0805_HV_NoOverlay 121.552,125.172 r0 top net-tie (schematic designator NT2)
NT2B "Net-Tie" Net-Tie_0805_HV_NoOverlay 78.852,124.985 r0 top net-tie (schematic designator NT2)
NT2C "Net-Tie" Net-Tie_0805_HV_NoOverlay 35.552,125.172 r0 top net-tie (schematic designator NT2)
NT2D "Net-Tie" Net-Tie_0805_HV_NoOverlay 12.406,53.666 r180 top net-tie (schematic designator NT2)
NT2E "Net-Tie" Net-Tie_0805_HV_NoOverlay 96.448,53.828 r180 top net-tie (schematic designator NT2)
NT3A "Net-Tie" Net-Tie_0805_HV_NoOverlay 111.057,126.875 r180 top net-tie (schematic designator NT3)
NT3B "Net-Tie" Net-Tie_0805_HV_NoOverlay 67.983,127.001 r180 top net-tie (schematic designator NT3)
NT3C "Net-Tie" Net-Tie_0805_HV_NoOverlay 24.824,126.409 r180 top net-tie (schematic designator NT3)
NT3D "Net-Tie" Net-Tie_0805_HV_NoOverlay 23.146,52.519 r0 top net-tie (schematic designator NT3)
NT3E "Net-Tie" Net-Tie_0805_HV_NoOverlay 107.457,52.355 r0 top net-tie (schematic designator NT3)
NT4A "Net-Tie" Net-Tie_0805_HV_NoOverlay 67.19,91.371 r270 top net-tie (schematic designator NT4)
NT4B "Net-Tie" Net-Tie_0805_HV_NoOverlay 131.684,92.199 r270 top net-tie (schematic designator NT4)
NT5A "Net-Tie" Net-Tie_0805_HV_NoOverlay 113.153,129.599 r180 top net-tie (schematic designator NT5)
NT5B "Net-Tie" Net-Tie_0805_HV_NoOverlay 70.453,129.412 r180 top net-tie (schematic designator NT5)
NT5C "Net-Tie" Net-Tie_0805_HV_NoOverlay 27.153,129.599 r180 top net-tie (schematic designator NT5)
NT5D "Net-Tie" Net-Tie_0805_HV_NoOverlay 20.819,49.733 r0 top net-tie (schematic designator NT5)
NT5E "Net-Tie" Net-Tie_0805_HV_NoOverlay 104.847,49.5 r0 top net-tie (schematic designator NT5)
NT6A "Net-Tie" Net-Tie_0805_HV_NoOverlay 52.355,88.883 r180 top net-tie (schematic designator NT6)
NT6B "Net-Tie" Net-Tie_0805_HV_NoOverlay 116.848,89.711 r180 top net-tie (schematic designator NT6)
NT7 "Net-Tie" Net-Tie_0805_HV_NoOverlay 63.288,52.2 r0 top net-tie
NT8A "Net-Tie" Net-Tie_0805_HV_NoOverlay 30.353,95.962 r180 top net-tie (schematic designator NT8)
NT8B "Net-Tie" Net-Tie_0805_HV_NoOverlay 94.847,96.791 r180 top net-tie (schematic designator NT8)
NT9A "Net-Tie" Net-Tie_0805_HV_NoOverlay 29.514,100.294 r180 top net-tie (schematic designator NT9)
NT9B "Net-Tie" Net-Tie_0805_HV_NoOverlay 94.007,101.123 r180 top net-tie (schematic designator NT9)
NT10 "Net-Tie" Net-Tie_0805_HV_NoOverlay 131.414,154.579 r90 top net-tie
NT10A "Net-Tie" Net-Tie_0805_HV_NoOverlay 53.108,73.346 r180 top net-tie (schematic designator NT10)
NT10B "Net-Tie" Net-Tie_0805_HV_NoOverlay 117.105,72.759 r90 top net-tie (schematic designator NT10)
NT11 "Net-Tie" Net-Tie_0805_HV_NoOverlay 129.205,154.613 r90 top net-tie
NT12 "Net-Tie" Net-Tie_0805_HV_NoOverlay 62.3,49.8 r0 top net-tie
NT13 "Net-Tie" Net-Tie_0805_HV_NoOverlay 51.706,52.316 r180 top net-tie
Q2A "CSD25404Q3" DQG0008A 25.572,96.368 r270 top value=-20V (schematic designator Q2)
Q2B "CSD25404Q3" DQG0008A 90.065,97.197 r270 top value=-20V (schematic designator Q2)
Q3A "CSD17585F5T" YJK0003A 20.111,96.607 r0 top value=30V (schematic designator Q3)
Q3B "CSD17585F5T" YJK0003A 84.604,97.436 r0 top value=30V (schematic designator Q3)
R1A "RN73C1J49K9BTG" FP-RN73C1J49K9BTG_0603-MFG 52.564,62.914 r90 top value=49.9k (schematic designator R1)
R1B "RN73C1J49K9BTG" FP-RN73C1J49K9BTG_0603-MFG 5.02,85.986 r0 top value=49.9k (schematic designator R1)
R2A "RN73C1J49K9BTG" FP-RN73C1J49K9BTG_0603-MFG 46.395,62.914 r270 top value=49.9k (schematic designator R2)
R2B "RN73C1J49K9BTG" FP-RN73C1J49K9BTG_0603-MFG 5.02,92.155 r180 top value=49.9k (schematic designator R2)
R3A "RN73C1J49K9BTG" FP-RN73C1J49K9BTG_0603-MFG 43.335,63.878 r270 top value=49.9k (schematic designator R3)
R3B "RN73C1J49K9BTG" FP-RN73C1J49K9BTG_0603-MFG 5.984,95.215 r180 top value=49.9k (schematic designator R3)
R4A "RN73C1J49K9BTG" FP-RN73C1J49K9BTG_0603-MFG 45.335,66.843 r90 top value=49.9k (schematic designator R4)
R4B "RN73C1J49K9BTG" FP-RN73C1J49K9BTG_0603-MFG 8.949,93.215 r0 top value=49.9k (schematic designator R4)
R5A "RN73C1J49K9BTG" FP-RN73C1J49K9BTG_0603-MFG 47.065,67.851 r90 top value=49.9k (schematic designator R5)
R5B "RN73C1J49K9BTG" FP-RN73C1J49K9BTG_0603-MFG 10.087,90.155 r0 top value=49.9k (schematic designator R5)
R6A "RN73C1J49K9BTG" FP-RN73C1J49K9BTG_0603-MFG 54.168,68.291 r90 top value=49.9k (schematic designator R6)
R6B "RN73C1J49K9BTG" FP-RN73C1J49K9BTG_0603-MFG 10.571,84.97 r0 top value=49.9k (schematic designator R6)
R7A "CRCW0603909RFKEA" 0603 73.192,103.443 r180 top value=909 (schematic designator R7)
R7B "CRCW0603909RFKEA" 0603 128.238,107.771 r180 top value=909 (schematic designator R7)
R8A "CRCW060310K2FKEA" 0603L 106.95,128.364 r180 top value=10.2k (schematic designator R8)
R8B "CRCW060310K2FKEA" 0603L 64.181,127.753 r180 top value=10.2k (schematic designator R8)
R8C "CRCW060310K2FKEA" 0603L 21.144,128.181 r180 top value=10.2k (schematic designator R8)
R8D "CRCW060310K2FKEA" 0603L 25.578,50.008 r0 top value=10.2k (schematic designator R8)
R8E "CRCW060310K2FKEA" 0603L 110.273,51.955 r90 top value=10.2k (schematic designator R8)
R9A "CRCW060310K2FKEA" 0603L 127.234,141.062 r180 top value=10.2k (schematic designator R9)
R9B "CRCW060310K2FKEA" 0603L 84.534,140.875 r180 top value=10.2k (schematic designator R9)
R9C "CRCW060310K2FKEA" 0603L 41.234,141.062 r180 top value=10.2k (schematic designator R9)
R9D "CRCW060310K2FKEA" 0603L 6.724,37.775 r0 top value=10.2k (schematic designator R9)
R9E "CRCW060310K2FKEA" 0603L 90.766,37.938 r0 top value=10.2k (schematic designator R9)
R10 "CRCW060310K2FKEA" 0603L 66.748,52.641 r0 top value=10.2k
R11 "CRCW060310K2FKEA" 0603L 71.871,70.133 r0 top value=10.2k
R12 "CRCW060310K2FKEA" 0603L 108.183,70.641 r0 top value=10.2k
R13A "CRCW0603205KFKEA" 0603L 53.974,85.663 r0 top value=205k (schematic designator R13)
R13B "CRCW0603205KFKEA" 0603L 118.791,87.501 r0 top value=205k (schematic designator R13)
R14 "CRCW060333R2FKEA" 0603L 18.882,114.99 r90 top value=33.2
R15 "CRCW06031R00FKEA" 0603L 70.253,43.695 r0 top value=1.00
R16A "CRCW06031R00FKEA" 0603L 106.169,131.482 r90 top value=1.00 (schematic designator R16)
R16B "CRCW06031R00FKEA" 0603L 63.47,131.295 r90 top value=1.00 (schematic designator R16)
R16C "CRCW06031R00FKEA" 0603L 20.169,131.482 r90 top value=1.00 (schematic designator R16)
R16D "CRCW06031R00FKEA" 0603L 27.789,47.356 r270 top value=1.00 (schematic designator R16)
R16E "CRCW06031R00FKEA" 0603L 111.831,47.518 r270 top value=1.00 (schematic designator R16)
R17A "CRCW060333R2FKEA" 0603L 109.093,132.916 r90 top value=33.2 (schematic designator R17)
R17B "CRCW060333R2FKEA" 0603L 66.394,132.729 r90 top value=33.2 (schematic designator R17)
R17C "CRCW060333R2FKEA" 0603L 23.093,132.916 r90 top value=33.2 (schematic designator R17)
R17D "CRCW060333R2FKEA" 0603L 24.864,45.922 r270 top value=33.2 (schematic designator R17)
R17E "CRCW060333R2FKEA" 0603L 108.907,46.084 r270 top value=33.2 (schematic designator R17)
R18A "CRCW06031R00FKEA" 0603L 125.601,132.26 r180 top value=1.00 (schematic designator R18)
R18B "CRCW06031R00FKEA" 0603L 82.902,132.073 r180 top value=1.00 (schematic designator R18)
R18C "CRCW06031R00FKEA" 0603L 39.601,132.26 r180 top value=1.00 (schematic designator R18)
R18D "CRCW06031R00FKEA" 0603L 8.357,46.578 r0 top value=1.00 (schematic designator R18)
R18E "CRCW06031R00FKEA" 0603L 92.399,46.74 r0 top value=1.00 (schematic designator R18)
R19 "CRCW060333R2FKEA" 0603L 67.543,43.697 r180 top value=33.2
R20A "CRCW060310K2FKEA" 0603L 112.444,137.793 r180 top value=10.2k (schematic designator R20)
R20B "CRCW060310K2FKEA" 0603L 69.744,137.606 r180 top value=10.2k (schematic designator R20)
R20C "CRCW060310K2FKEA" 0603L 26.444,137.793 r180 top value=10.2k (schematic designator R20)
R20D "CRCW060310K2FKEA" 0603L 21.514,41.045 r0 top value=10.2k (schematic designator R20)
R20E "CRCW060310K2FKEA" 0603L 105.556,41.207 r0 top value=10.2k (schematic designator R20)
R21 "CRCW060356R2FKEA" 0603L 80.131,43.06 r270 top value=56.2
R22A "CRCW060356R2FKEA" 0603L 97.534,135.435 r90 top value=56.2 (schematic designator R22)
R22B "CRCW060356R2FKEA" 0603L 54.835,135.248 r90 top value=56.2 (schematic designator R22)
R22C "CRCW060356R2FKEA" 0603L 11.534,135.435 r90 top value=56.2 (schematic designator R22)
R22D "CRCW060356R2FKEA" 0603L 36.424,43.403 r270 top value=56.2 (schematic designator R22)
R22E "CRCW060356R2FKEA" 0603L 120.466,43.565 r270 top value=56.2 (schematic designator R22)
R23A "CRCW060356R2FKEA" 0603L 115.302,135.455 r90 top value=56.2 (schematic designator R23)
R23B "CRCW060356R2FKEA" 0603L 72.603,135.268 r90 top value=56.2 (schematic designator R23)
R23C "CRCW060356R2FKEA" 0603L 29.302,135.455 r90 top value=56.2 (schematic designator R23)
R23D "CRCW060356R2FKEA" 0603L 18.656,43.382 r270 top value=56.2 (schematic designator R23)
R23E "CRCW060356R2FKEA" 0603L 102.698,43.545 r270 top value=56.2 (schematic designator R23)
R24A "CRCW060356R2FKEA" 0603L 101.344,135.435 r90 top value=56.2 (schematic designator R24)
R24B "CRCW060356R2FKEA" 0603L 58.645,135.248 r90 top value=56.2 (schematic designator R24)
R24C "CRCW060356R2FKEA" 0603L 15.344,135.435 r90 top value=56.2 (schematic designator R24)
R24D "CRCW060356R2FKEA" 0603L 32.614,43.403 r270 top value=56.2 (schematic designator R24)
R24E "CRCW060356R2FKEA" 0603L 116.656,43.565 r270 top value=56.2 (schematic designator R24)
R25A "CRCW060356R2FKEA" 0603L 119.113,135.455 r90 top value=56.2 (schematic designator R25)
R25B "CRCW060356R2FKEA" 0603L 76.413,135.268 r90 top value=56.2 (schematic designator R25)
R25C "CRCW060356R2FKEA" 0603L 33.113,135.455 r90 top value=56.2 (schematic designator R25)
R25D "CRCW060356R2FKEA" 0603L 14.845,43.382 r270 top value=56.2 (schematic designator R25)
R25E "CRCW060356R2FKEA" 0603L 98.887,43.545 r270 top value=56.2 (schematic designator R25)
R26A "CRCW060316K2FKEA" 0603L 56.499,83.077 r90 top value=16.2k (schematic designator R26)
R26B "CRCW060316K2FKEA" 0603L 120.706,83.817 r90 top value=16.2k (schematic designator R26)
R27 "CRCW060356R2FKEA" 0603L 74.522,42.94 r270 top value=56.2
R28A "CRCW0603205KFKEA" 0603L 56.616,86.258 r90 top value=205k (schematic designator R28)
R28B "CRCW0603205KFKEA" 0603L 121.922,87.086 r90 top value=205k (schematic designator R28)
R29 "CRCW060310K2FKEA" 0603L 63.238,39.568 r90 top value=10.2k
R30 "CRCW06031R00FKEA" 0603L 49.687,43.615 r0 top value=1.00
R31A "CRCW12061R00FKEA" 1206L 57.301,89.138 r180 top value=1.00 (schematic designator R31)
R31B "CRCW12061R00FKEA" 1206L 121.795,89.88 r180 top value=1.00 (schematic designator R31)
R32 "CRCW060333R2FKEA" 0603L 23.957,114.99 r90 top value=33.2
R33 "CRCW060310K2FKEA" 0603L 49.212,37.525 r0 top value=10.2k
R34 "CRCW060356R2FKEA" 0603L 60.768,43.805 r270 top value=56.2
R34A "CRCW0603732KFKEA" 0603 55.374,110.734 r180 top value=732k (schematic designator R34)
R34B "CRCW0603732KFKEA" 0603 110.42,115.061 r180 top value=732k (schematic designator R34)
R35 "CRCW060356R2FKEA" 0603L 55.437,43.69 r270 top value=56.2
R36A "CRCW0603100KFKEA" 0603L 36.987,99.255 r90 top value=100k (schematic designator R36)
R36B "CRCW0603100KFKEA" 0603L 101.481,100.083 r90 top value=100k (schematic designator R36)
R37A "CRCW060388K7FKEA" 0603L 45.621,100.144 r0 top value=88.7k (schematic designator R37)
R37B "CRCW060388K7FKEA" 0603L 110.115,100.973 r0 top value=88.7k (schematic designator R37)
R38A "CRCW06032K00FKEA" 0603L 43.085,100.144 r0 top value=2.00k (schematic designator R38)
R38B "CRCW06032K00FKEA" 0603L 107.579,100.973 r0 top value=2.00k (schematic designator R38)
R39A "CRCW060310K2FKEA" 0603L 41.69,101.541 r0 top value=10.2k (schematic designator R39)
R39B "CRCW060310K2FKEA" 0603L 106.184,102.369 r0 top value=10.2k (schematic designator R39)
R40A "RE0201BRE07100KL" FP-RE0201BRE07100KL_0201-MFG 67.502,102.723 r0 top value=100k (schematic designator R40)
R40B "RE0201BRE07100KL" FP-RE0201BRE07100KL_0201-MFG 122.499,106.968 r0 top value=100k (schematic designator R40)
R41A "RNCF0603TKY10K0" 0603 64.31,102.866 r180 top value=10.0k (schematic designator R41)
R41B "RNCF0603TKY10K0" 0603 119.357,107.193 r180 top value=10.0k (schematic designator R41)
R42A "CRCW060311K5FKEA" 0603L 25.699,92.289 r0 top value=11.5k (schematic designator R42)
R42B "CRCW060311K5FKEA" 0603L 90.192,93.118 r0 top value=11.5k (schematic designator R42)
R43A "CRCW060311K5FKEA" 0603L 20.873,92.289 r0 top value=11.5k (schematic designator R43)
R43B "CRCW060311K5FKEA" 0603L 85.366,93.118 r0 top value=11.5k (schematic designator R43)
R44A "CRCW06038K06FKEA" 0603L 22.651,96.353 r270 top value=8.06k (schematic designator R44)
R44B "CRCW06038K06FKEA" 0603L 87.144,97.182 r270 top value=8.06k (schematic designator R44)
R45A "CRCW06034K42FKEA" 0603L 43.085,91.889 r90 top value=4.42k (schematic designator R45)
R45B "CRCW06034K42FKEA" 0603L 107.579,92.717 r90 top value=4.42k (schematic designator R45)
R46A "CRCW06038K06FKEA" 0603L 21.889,98.258 r0 top value=8.06k (schematic designator R46)
R46B "CRCW06038K06FKEA" 0603L 86.382,99.087 r0 top value=8.06k (schematic designator R46)
R47A "CRCW060344K2FKEA" 0603L 39.822,97.858 r180 top value=44.2k (schematic designator R47)
R47B "CRCW060344K2FKEA" 0603L 104.316,98.686 r180 top value=44.2k (schematic designator R47)
R48A "CRCW06036K04FKEA" 0603L 40.089,99.255 r0 top value=6.04k (schematic designator R48)
R48B "CRCW06036K04FKEA" 0603L 104.583,100.083 r0 top value=6.04k (schematic designator R48)
R49A "CRCW06034K53FKEA" 0603L 16.809,94.194 r90 top value=4.53k (schematic designator R49)
R49B "CRCW06034K53FKEA" 0603L 81.302,95.023 r90 top value=4.53k (schematic designator R49)
R50 "CRCW060333R2FKEA" 0603L 25.684,64.129 r0 top value=33.2
R51A "Resistor" 0603S 73.133,110.992 r0 top value=0 (schematic designator R51)
R51B "Resistor" 0603S 128.179,115.32 r0 top value=0 (schematic designator R51)
R52A "Resistor" 0603S 61.27,103.333 r0 top value=0 (schematic designator R52)
R52B "Resistor" 0603S 116.317,107.661 r0 top value=0 (schematic designator R52)
R53 "CRCW060333R2FKEA" 0603L 34.242,106.499 r90 top value=33.2
R54 "CRCW060333R2FKEA" 0603L 34.117,114.99 r90 top value=33.2
R55 "CRCW060333R2FKEA" 0603L 37.094,106.499 r90 top value=33.2
R56 "CRCW060333R2FKEA" 0603L 39.135,106.499 r90 top value=33.2
R57 "CRCW060333R2FKEA" 0603L 39.135,114.99 r90 top value=33.2
R58 "CRCW060333R2FKEA" 0603L 95.01,71.811 r90 top value=33.2
R59 "CRCW060333R2FKEA" 0603L 97.617,63.516 r90 top value=33.2
R60 "CRCW060333R2FKEA" 0603L 97.617,71.811 r90 top value=33.2
R61 "CRCW060333R2FKEA" 0603L 100.207,71.811 r90 top value=33.2
R62 "CRCW060333R2FKEA" 0603L 99.497,107.296 r0 top value=33.2
R63 "CRCW060333R2FKEA" 0603L 102,114.353 r180 top value=33.2
R64 "CRCW060333R2FKEA" 0603L 133.163,60.121 r270 top value=33.2
R65 "CRCW060333R2FKEA" 0603L 130.571,60.121 r270 top value=33.2
R143A "CRCW0603909RFKEA" 0603 64.36,101.136 r0 top value=909 (schematic designator R143)
R143B "CRCW0603909RFKEA" 0603 119.407,105.464 r0 top value=909 (schematic designator R143)
R145A "RR0816P-104-D" 0603_HR 55.38,112.618 r0 top value=100k (schematic designator R145)
R145B "RR0816P-104-D" 0603_HR 110.427,116.945 r0 top value=100k (schematic designator R145)
R149A "RE0201BRE07100KL" FP-RE0201BRE07100KL_0201-MFG 52.316,110.569 r0 top value=100k (schematic designator R149)
R149B "RE0201BRE07100KL" FP-RE0201BRE07100KL_0201-MFG 107.363,114.896 r0 top value=100k (schematic designator R149)
T1A "PE-68386NL" PULSE_PE-68386NL 99.439,142.674 r90 top value=785uH (schematic designator T1)
T1B "PE-68386NL" PULSE_PE-68386NL 56.74,142.487 r90 top value=785uH (schematic designator T1)
T1C "PE-68386NL" PULSE_PE-68386NL 13.439,142.674 r90 top value=785uH (schematic designator T1)
T1D "PE-68386NL" PULSE_PE-68386NL 34.519,36.164 r270 top value=785uH (schematic designator T1)
T1E "PE-68386NL" PULSE_PE-68386NL 118.561,36.326 r270 top value=785uH (schematic designator T1)
T2A "PE-68386NL" PULSE_PE-68386NL 117.208,142.694 r90 top value=785uH (schematic designator T2)
T2B "PE-68386NL" PULSE_PE-68386NL 74.508,142.507 r90 top value=785uH (schematic designator T2)
T2C "PE-68386NL" PULSE_PE-68386NL 31.208,142.694 r90 top value=785uH (schematic designator T2)
T2D "PE-68386NL" PULSE_PE-68386NL 16.75,36.143 r270 top value=785uH (schematic designator T2)
T2E "PE-68386NL" PULSE_PE-68386NL 100.792,36.306 r270 top value=785uH (schematic designator T2)
T3 "PE-68386NL" PULSE_PE-68386NL 77.508,35.589 r270 top value=785uH
T4 "PE-68386NL" PULSE_PE-68386NL 58.175,35.583 r270 top value=785uH
TP1 "5004" Keystone5004 79.836,19.854 r0 top
TP2 "5004" Keystone5004 81.247,45.906 r0 top
TP3 "5004" Keystone5004 74.547,46.269 r0 top
TP4 "5004" Keystone5004 75.065,19.854 r0 top
TP5 "5004" Keystone5004 77.51,48.186 r0 top
TP6 "5001" Keystone5001 50.648,31.94 r0 top
TP7 "5004" Keystone5004 60.594,19.898 r0 top
TP8 "5004" Keystone5004 60.9,46.792 r0 top
TP9 "5004" Keystone5004 54.09,47.249 r0 top
TP10 "5004" Keystone5004 56.091,19.898 r0 top
TP11 "5004" Keystone5004 58.102,48.142 r0 top
TP16A "5004" Keystone5004 95.375,132.895 r180 top (schematic designator TP16)
TP16B "5004" Keystone5004 52.676,132.708 r180 top (schematic designator TP16)
TP16C "5004" Keystone5004 9.375,132.895 r180 top (schematic designator TP16)
TP16D "5004" Keystone5004 38.583,45.943 r0 top (schematic designator TP16)
TP16E "5004" Keystone5004 122.625,46.105 r0 top (schematic designator TP16)
TP17A "5004" Keystone5004 103.503,132.895 r180 top (schematic designator TP17)
TP17B "5004" Keystone5004 60.804,132.708 r180 top (schematic designator TP17)
TP17C "5004" Keystone5004 17.503,132.895 r180 top (schematic designator TP17)
TP17D "5004" Keystone5004 30.455,45.943 r0 top (schematic designator TP17)
TP17E "5004" Keystone5004 114.497,46.105 r0 top (schematic designator TP17)
TP18A "5004" Keystone5004 114.668,132.535 r180 top (schematic designator TP18)
TP18B "5004" Keystone5004 71.968,132.348 r180 top (schematic designator TP18)
TP18C "5004" Keystone5004 28.668,132.535 r180 top (schematic designator TP18)
TP18D "5004" Keystone5004 19.29,46.303 r0 top (schematic designator TP18)
TP18E "5004" Keystone5004 103.332,46.465 r0 top (schematic designator TP18)
TP19A "5004" Keystone5004 121.272,132.915 r180 top (schematic designator TP19)
TP19B "5004" Keystone5004 78.572,132.728 r180 top (schematic designator TP19)
TP19C "5004" Keystone5004 35.272,132.915 r180 top (schematic designator TP19)
TP19D "5004" Keystone5004 12.686,45.922 r0 top (schematic designator TP19)
TP19E "5004" Keystone5004 96.728,46.085 r0 top (schematic designator TP19)
TP20A "5001" Keystone5001 124.413,154.123 r180 top (schematic designator TP20)
TP20B "5001" Keystone5001 81.713,153.936 r180 top (schematic designator TP20)
TP20C "5001" Keystone5001 38.413,154.123 r180 top (schematic designator TP20)
TP20D "5001" Keystone5001 9.545,24.714 r0 top (schematic designator TP20)
TP20E "5001" Keystone5001 93.587,24.877 r0 top (schematic designator TP20)
TP21A "5004" Keystone5004 99.555,130.756 r180 top (schematic designator TP21)
TP21B "5004" Keystone5004 56.855,130.569 r180 top (schematic designator TP21)
TP21C "5004" Keystone5004 13.555,130.756 r180 top (schematic designator TP21)
TP21D "5004" Keystone5004 34.403,48.081 r0 top (schematic designator TP21)
TP21E "5004" Keystone5004 118.445,48.244 r0 top (schematic designator TP21)
TP22A "5004" Keystone5004 118.126,130.838 r180 top (schematic designator TP22)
